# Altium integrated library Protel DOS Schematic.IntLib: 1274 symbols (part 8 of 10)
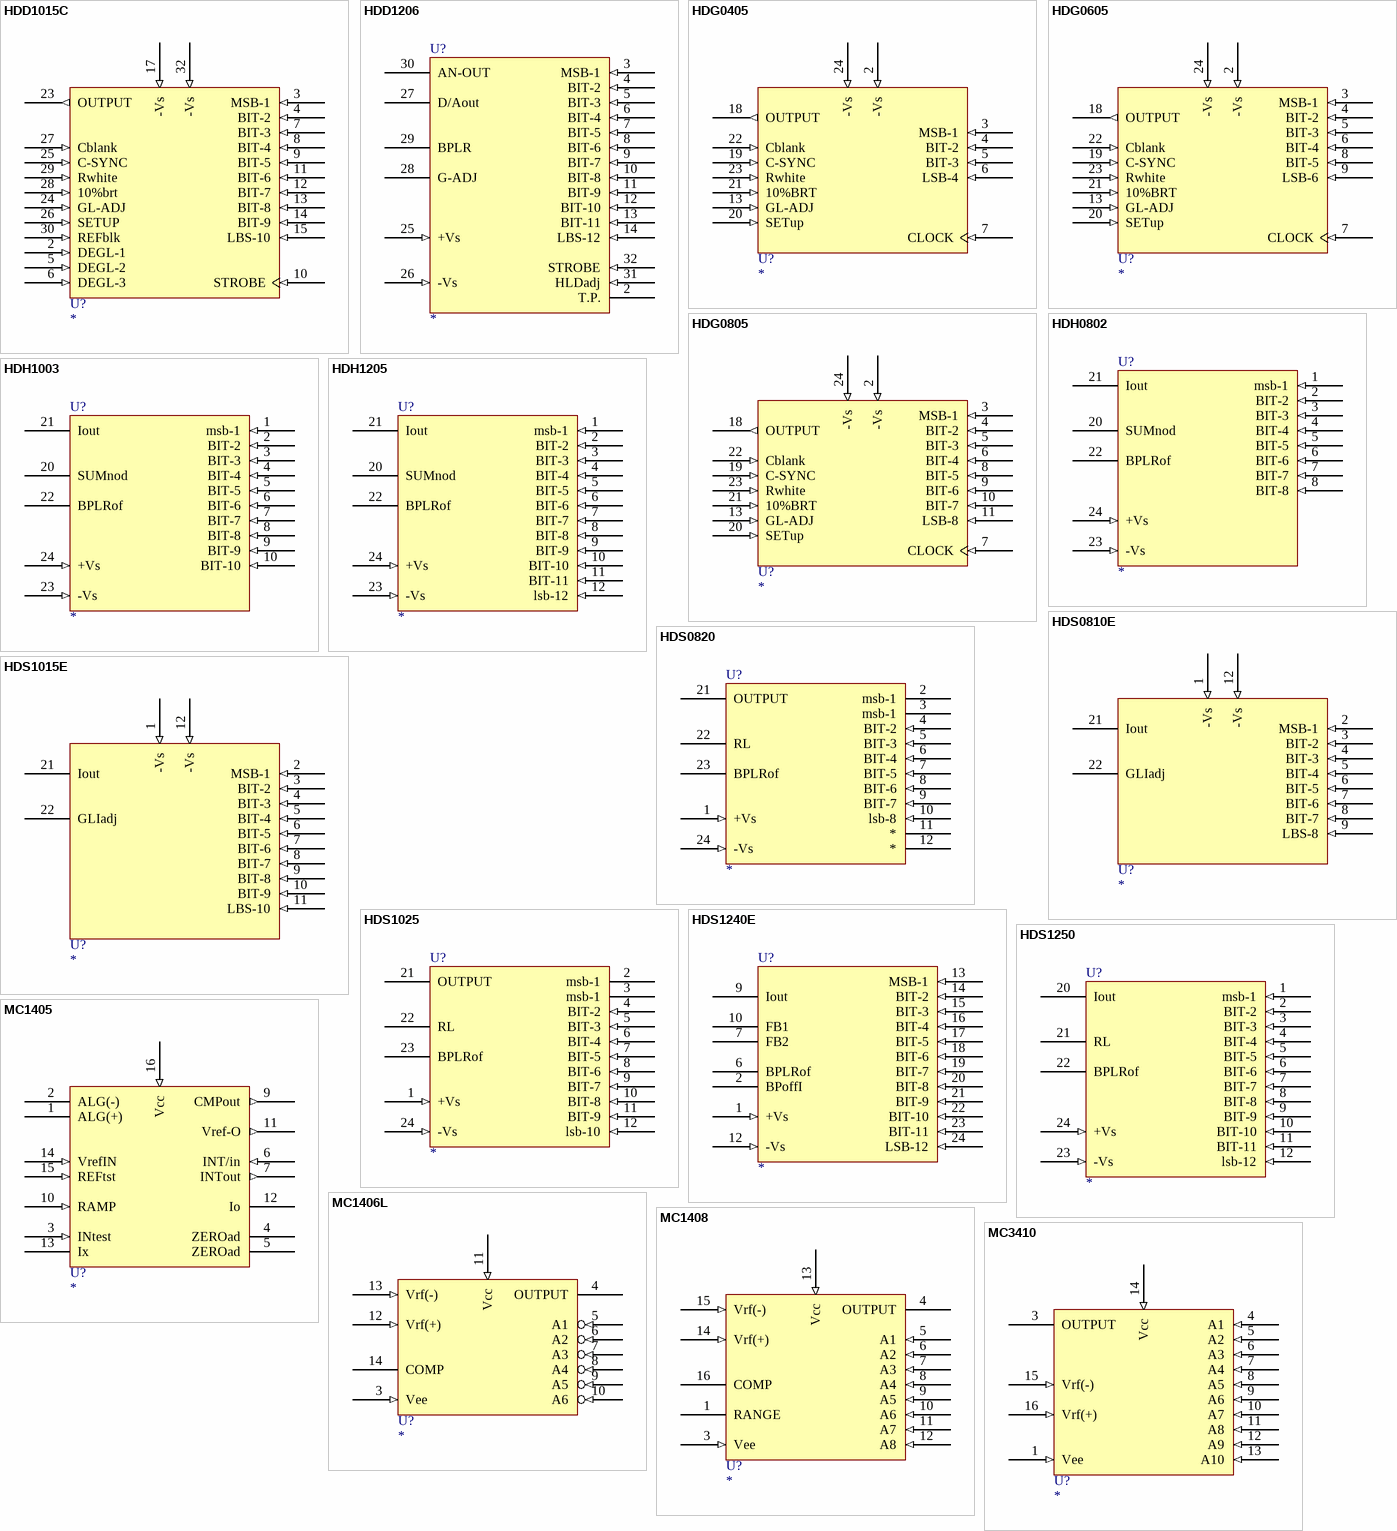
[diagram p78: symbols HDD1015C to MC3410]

## HDG0605
designator U?
footprint HY24
pins: 1 GND (power) hidden to GND, 2 -Vs (in), 3 MSB-1 (in), 4 BIT-2 (in), 5 BIT-3 (in), 6 BIT-4 (in), 7 CLOCK (in), 8 BIT-5 (in), 9 LSB-6 (in), 12 GND (power) hidden to GND, 13 GL-ADJ (in), 14 GND (power) hidden to GND, 15 GND (power) hidden to GND, 16 GND (power) hidden to GND, 17 GND (power) hidden to GND, 18 OUTPUT (out), 19 C-SYNC (in), 20 SETup (in), 21 10%BRT (in), 22 Cblank (in), 23 Rwhite (in), 24 -Vs (in)
2 alternate drawings of the same symbol

## HDG0805
designator U?
footprint HY24
pins: 1 GND (power) hidden to GND, 2 -Vs (in), 3 MSB-1 (in), 4 BIT-2 (in), 5 BIT-3 (in), 6 BIT-4 (in), 7 CLOCK (in), 8 BIT-5 (in), 9 BIT-6 (in), 10 BIT-7 (in), 11 LSB-8 (in), 12 GND (power) hidden to GND, 13 GL-ADJ (in), 14 GND (power) hidden to GND, 15 GND (power) hidden to GND, 16 GND (power) hidden to GND, 17 GND (power) hidden to GND, 18 OUTPUT (out), 19 C-SYNC (in), 20 SETup (in), 21 10%BRT (in), 22 Cblank (in), 23 Rwhite (in), 24 -Vs (in)
2 alternate drawings of the same symbol

## HDH0802
designator U?
footprint HY24
pins: 1 msb-1 (in), 2 BIT-2 (in), 3 BIT-3 (in), 4 BIT-4 (in), 5 BIT-5 (in), 6 BIT-6 (in), 7 BIT-7 (in), 8 BIT-8 (in), 9 GND (power) hidden to GND, 10 GND (power) hidden to GND, 11 GND (power) hidden to GND, 12 GND (power) hidden to GND, 13 GND (power) hidden to GND, 14 GND (power) hidden to GND, 15 GND (power) hidden to GND, 16 GND (power) hidden to GND, 17 GND (power) hidden to GND, 18 GND (power) hidden to GND, 19 GND (power) hidden to GND, 20 SUMnod, 21 Iout, 22 BPLRof, 23 -Vs (in), 24 +Vs (in)
2 alternate drawings of the same symbol

## HDH1003
designator U?
footprint HY24
pins: 1 msb-1 (in), 2 BIT-2 (in), 3 BIT-3 (in), 4 BIT-4 (in), 5 BIT-5 (in), 6 BIT-6 (in), 7 BIT-7 (in), 8 BIT-8 (in), 9 BIT-9 (in), 10 BIT-10 (in), 11 GND (power) hidden to GND, 12 GND (power) hidden to GND, 13 GND (power) hidden to GND, 14 GND (power) hidden to GND, 15 GND (power) hidden to GND, 16 GND (power) hidden to GND, 17 GND (power) hidden to GND, 18 GND (power) hidden to GND, 19 GND (power) hidden to GND, 20 SUMnod, 21 Iout, 22 BPLRof, 23 -Vs (in), 24 +Vs (in)
2 alternate drawings of the same symbol

## HDH1205
designator U?
footprint HY24
pins: 1 msb-1 (in), 2 BIT-2 (in), 3 BIT-3 (in), 4 BIT-4 (in), 5 BIT-5 (in), 6 BIT-6 (in), 7 BIT-7 (in), 8 BIT-8 (in), 9 BIT-9 (in), 10 BIT-10 (in), 11 BIT-11 (in), 12 lsb-12 (in), 13 GND (power) hidden to GND, 14 GND (power) hidden to GND, 15 GND (power) hidden to GND, 16 GND (power) hidden to GND, 17 GND (power) hidden to GND, 18 GND (power) hidden to GND, 19 GND (power) hidden to GND, 20 SUMnod, 21 Iout, 22 BPLRof, 23 -Vs (in), 24 +Vs (in)
2 alternate drawings of the same symbol

## HDS0810E
designator U?
footprint HY24
pins: 1 -Vs (in), 2 MSB-1 (in), 3 BIT-2 (in), 4 BIT-3 (in), 5 BIT-4 (in), 6 BIT-5 (in), 7 BIT-6 (in), 8 BIT-7 (in), 9 LBS-8 (in), 12 -Vs (in), 13 GND (power) hidden to GND, 14 GND (power) hidden to GND, 15 GND (power) hidden to GND, 16 GND (power) hidden to GND, 17 GND (power) hidden to GND, 18 GND (power) hidden to GND, 19 GND (power) hidden to GND, 20 GND (power) hidden to GND, 21 Iout, 22 GLIadj, 23 GND (power) hidden to GND, 24 GND (power) hidden to GND
2 alternate drawings of the same symbol

## HDS0820
designator U?
footprint HY24
pins: 1 +Vs (in), 2 msb-1, 3 msb-1, 4 BIT-2 (in), 5 BIT-3 (in), 6 BIT-4 (in), 7 BIT-5 (in), 8 BIT-6 (in), 9 BIT-7 (in), 10 lsb-8 (in), 11 *, 12 *, 13 GND (power) hidden to GND, 14 GND (power) hidden to GND, 15 GND (power) hidden to GND, 16 GND (power) hidden to GND, 17 GND (power) hidden to GND, 18 GND (power) hidden to GND, 19 GND (power) hidden to GND, 20 GND (power) hidden to GND, 21 OUTPUT, 22 RL, 23 BPLRof, 24 -Vs (in)
2 alternate drawings of the same symbol

## HDS1015E
designator U?
footprint HY24
pins: 1 -Vs (in), 2 MSB-1 (in), 3 BIT-2 (in), 4 BIT-3 (in), 5 BIT-4 (in), 6 BIT-5 (in), 7 BIT-6 (in), 8 BIT-7 (in), 9 BIT-8 (in), 10 BIT-9 (in), 11 LBS-10 (in), 12 -Vs (in), 13 GND (power) hidden to GND, 14 GND (power) hidden to GND, 15 GND (power) hidden to GND, 16 GND (power) hidden to GND, 17 GND (power) hidden to GND, 18 GND (power) hidden to GND, 19 GND (power) hidden to GND, 20 GND (power) hidden to GND, 21 Iout, 22 GLIadj, 23 GND (power) hidden to GND, 24 GND (power) hidden to GND
2 alternate drawings of the same symbol

## HDS1025
designator U?
footprint HY24
pins: 1 +Vs (in), 2 msb-1, 3 msb-1, 4 BIT-2 (in), 5 BIT-3 (in), 6 BIT-4 (in), 7 BIT-5 (in), 8 BIT-6 (in), 9 BIT-7 (in), 10 BIT-8 (in), 11 BIT-9 (in), 12 lsb-10 (in), 13 GND (power) hidden to GND, 14 GND (power) hidden to GND, 15 GND (power) hidden to GND, 16 GND (power) hidden to GND, 17 GND (power) hidden to GND, 18 GND (power) hidden to GND, 19 GND (power) hidden to GND, 20 GND (power) hidden to GND, 21 OUTPUT, 22 RL, 23 BPLRof, 24 -Vs (in)
2 alternate drawings of the same symbol

## HDS1240E
designator U?
footprint HY24
pins: 1 +Vs (in), 2 BPoffI, 3 GND (power) hidden to GND, 4 GND (power) hidden to GND, 5 GND (power) hidden to GND, 6 BPLRof, 7 FB2, 9 Iout, 10 FB1, 12 -Vs (in), 13 MSB-1 (in), 14 BIT-2 (in), 15 BIT-3 (in), 16 BIT-4 (in), 17 BIT-5 (in), 18 BIT-6 (in), 19 BIT-7 (in), 20 BIT-8 (in), 21 BIT-9 (in), 22 BIT-10 (in), 23 BIT-11 (in), 24 LSB-12 (in)
2 alternate drawings of the same symbol

## HDS1250
designator U?
footprint HY24
pins: 1 msb-1 (in), 2 BIT-2 (in), 3 BIT-3 (in), 4 BIT-4 (in), 5 BIT-5 (in), 6 BIT-6 (in), 7 BIT-7 (in), 8 BIT-8 (in), 9 BIT-9 (in), 10 BIT-10 (in), 11 BIT-11 (in), 12 lsb-12 (in), 13 GND (power) hidden to GND, 14 GND (power) hidden to GND, 15 GND (power) hidden to GND, 16 GND (power) hidden to GND, 17 GND (power) hidden to GND, 18 GND (power) hidden to GND, 19 GND (power) hidden to GND, 20 Iout, 21 RL, 22 BPLRof, 23 -Vs (in), 24 +Vs (in)
2 alternate drawings of the same symbol

## MC1405
designator U?
footprint DIP-16
pins: 1 ALG(+), 2 ALG(-), 3 INtest (in), 4 ZEROad, 5 ZEROad, 6 INT/in (in), 7 INTout (out), 8 GND (power) hidden to GND, 9 CMPout (out), 10 RAMP (in), 11 Vref-O (out), 12 Io, 13 Ix, 14 VrefIN (in), 15 REFtst (in), 16 Vcc (in)
2 alternate drawings of the same symbol

## MC1406L
designator U?
footprint DIP-14
pins: 2 GND (power) hidden to GND, 3 Vee (in), 4 OUTPUT, 5 A1 (in), 6 A2 (in), 7 A3 (in), 8 A4 (in), 9 A5 (in), 10 A6 (in), 11 Vcc (in), 12 Vrf(+) (in), 13 Vrf(-) (in), 14 COMP
2 alternate drawings of the same symbol

## MC1408
designator U?
footprint DIP-16
pins: 1 RANGE, 2 GND (power) hidden to GND, 3 Vee (in), 4 OUTPUT, 5 A1 (in), 6 A2 (in), 7 A3 (in), 8 A4 (in), 9 A5 (in), 10 A6 (in), 11 A7 (in), 12 A8 (in), 13 Vcc (in), 14 Vrf(+) (in), 15 Vrf(-) (in), 16 COMP
2 alternate drawings of the same symbol

## MC3410
designator U?
footprint DIP-16
pins: 1 Vee (in), 2 GND (power) hidden to GND, 3 OUTPUT, 4 A1 (in), 5 A2 (in), 6 A3 (in), 7 A4 (in), 8 A5 (in), 9 A6 (in), 10 A7 (in), 11 A8 (in), 12 A9 (in), 13 A10 (in), 14 Vcc (in), 15 Vrf(-) (in), 16 Vrf(+) (in)
2 alternate drawings of the same symbol

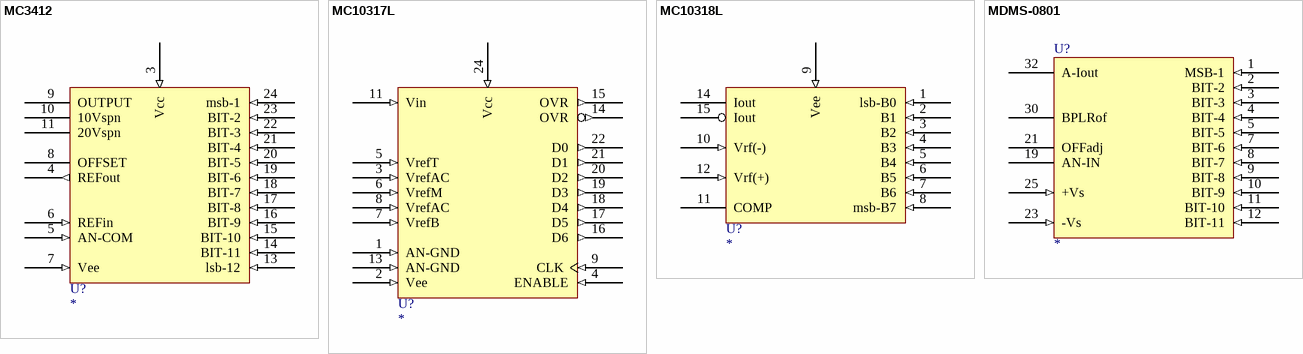
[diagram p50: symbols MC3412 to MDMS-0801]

## MC3412
designator U?
footprint DIP-24
pins: 3 Vcc (in), 4 REFout (out), 5 AN-COM (in), 6 REFin (in), 7 Vee (in), 8 OFFSET, 9 OUTPUT, 10 10Vspn, 11 20Vspn, 12 GND (power) hidden to GND, 13 lsb-12 (in), 14 BIT-11 (in), 15 BIT-10 (in), 16 BIT-9 (in), 17 BIT-8 (in), 18 BIT-7 (in), 19 BIT-6 (in), 20 BIT-5 (in), 21 BIT-4 (in), 22 BIT-3 (in), 23 BIT-2 (in), 24 msb-1 (in)
2 alternate drawings of the same symbol

## MC10317L
designator U?
footprint DIP-24
pins: 1 AN-GND (in), 2 Vee (in), 3 VrefAC (in), 4 ENABLE (in), 5 VrefT (in), 6 VrefM (in), 7 VrefB (in), 8 VrefAC (in), 9 CLK (in), 11 Vin (in), 13 AN-GND (in), 14 OVR (out), 15 OVR (out), 16 D6 (out), 17 D5 (out), 18 D4 (out), 19 D3 (out), 20 D2 (out), 21 D1 (out), 22 D0 (out), 23 GND (power) hidden to GND, 24 Vcc (in)
2 alternate drawings of the same symbol

## MC10318L
designator U?
footprint DIP-16
pins: 1 lsb-B0 (in), 2 B1 (in), 3 B2 (in), 4 B3 (in), 5 B4 (in), 6 B5 (in), 7 B6 (in), 8 msb-B7 (in), 9 Vee (in), 10 Vrf(-) (in), 11 COMP, 12 Vrf(+) (in), 14 Iout, 15 Iout, 16 GND (power) hidden to GND
2 alternate drawings of the same symbol

## MDMS-0801
designator U?
footprint HYB32
pins: 1 MSB-1 (in), 2 BIT-2 (in), 3 BIT-3 (in), 4 BIT-4 (in), 5 BIT-5 (in), 7 BIT-6 (in), 8 BIT-7 (in), 9 BIT-8 (in), 10 BIT-9 (in), 11 BIT-10 (in), 12 BIT-11 (in), 19 AN-IN, 21 OFFadj, 23 -Vs (in), 25 +Vs (in), 28 GND (power) hidden to GND, 30 BPLRof, 32 A-Iout
2 alternate drawings of the same symbol


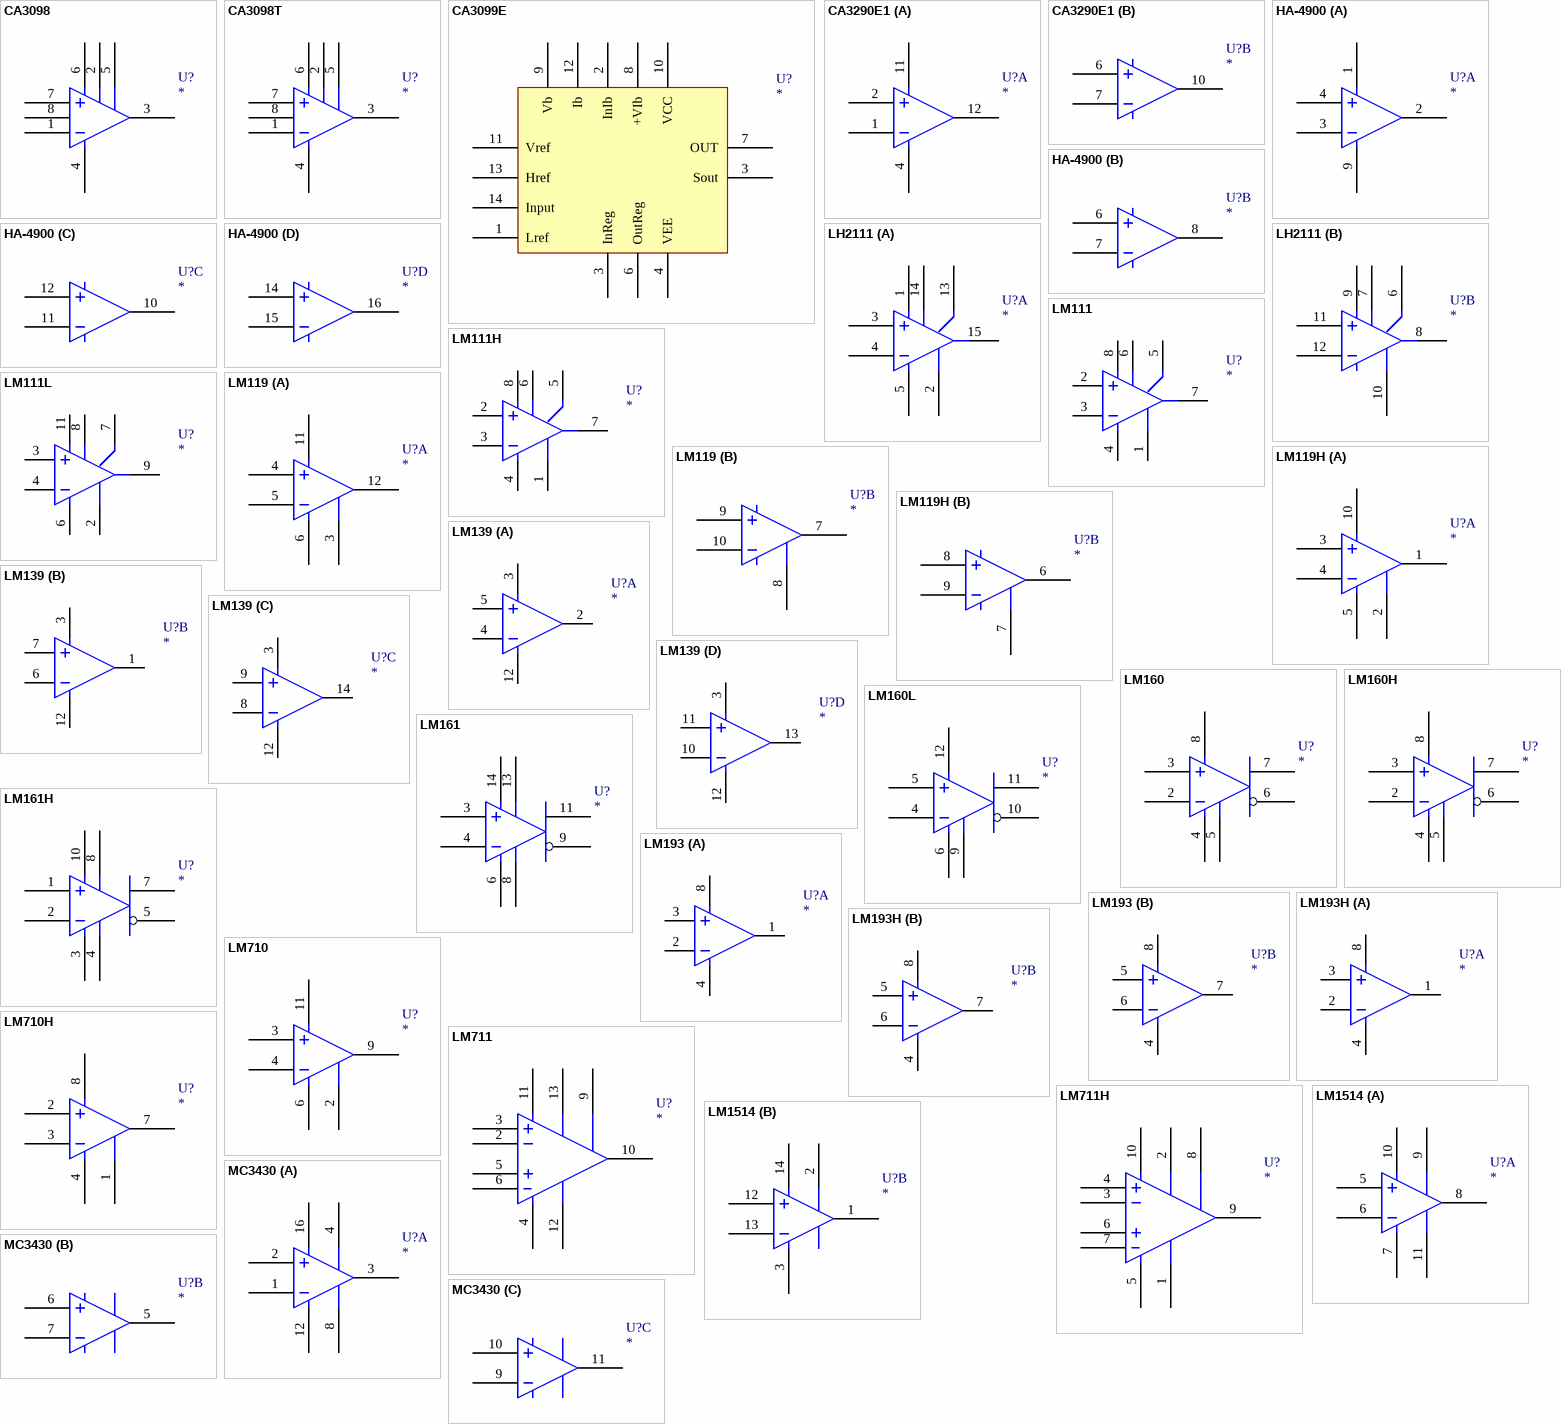
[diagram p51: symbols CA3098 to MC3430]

## CA3098
designator U?
footprint DIP-8
pins: 1, 2, 3, 4, 5, 6, 7, 8
2 alternate drawings of the same symbol

## CA3098T
designator U?
footprint METAL8
pins: 1, 2, 3, 4, 5, 6, 7, 8
2 alternate drawings of the same symbol

## CA3099E
designator U?
footprint DIP-14
pins: 1 Lref, 2 InIb, 3 Sout, 3 InReg, 4 VEE, 6 OutReg, 7 OUT, 8 +VIb, 9 Vb, 10 VCC, 11 Vref, 12 Ib, 13 Href, 14 Input
2 alternate drawings of the same symbol

## CA3290E1
designator U?
footprint DIP-14
part A pins: 1, 2, 4, 11, 12
part B pins: 6, 7, 10
2 alternate drawings of the same symbol

## HA-4900
designator U?
footprint DIP-16
part A pins: 1, 2, 3, 4, 9
part B pins: 6, 7, 8
part C pins: 10, 11, 12
part D pins: 14, 15, 16
2 alternate drawings of the same symbol

## LH2111
designator U?
footprint DIP-16
part A pins: 1, 2, 3, 4, 5, 13, 14, 15
part B pins: 6, 7, 8, 9, 10, 11, 12
2 alternate drawings of the same symbol

## LM111
designator U?
footprint DIP-8
pins: 1, 2, 3, 4, 5, 6, 7, 8
2 alternate drawings of the same symbol

## LM111H
designator U?
footprint METAL8
pins: 1, 2, 3, 4, 5, 6, 7, 8
2 alternate drawings of the same symbol

## LM111L
designator U?
footprint DIP-14
pins: 2, 3, 4, 6, 7, 8, 9, 11
2 alternate drawings of the same symbol

## LM119
designator U?
footprint DIP-14
part A pins: 3, 4, 5, 6, 11, 12
part B pins: 7, 8, 9, 10
2 alternate drawings of the same symbol

## LM119H
designator U?
footprint METAL10
part A pins: 1, 2, 3, 4, 5, 10
part B pins: 6, 7, 8, 9
2 alternate drawings of the same symbol

## LM139
designator U?
footprint DIP-14
part A pins: 2, 3, 4, 5, 12
part B pins: 1, 3, 6, 7, 12
part C pins: 3, 8, 9, 12, 14
part D pins: 3, 10, 11, 12, 13
2 alternate drawings of the same symbol

## LM160
designator U?
footprint DIP-8
pins: 2, 3, 4, 5, 6, 7, 8
2 alternate drawings of the same symbol

## LM160H
designator U?
footprint METAL8
pins: 2, 3, 4, 5, 6, 7, 8
2 alternate drawings of the same symbol

## LM160L
designator U?
footprint DIP-14
pins: 4, 5, 6, 9, 10, 11, 12
2 alternate drawings of the same symbol

## LM161
designator U?
footprint DIP-14
pins: 3, 4, 6, 8, 9, 11, 13, 14
2 alternate drawings of the same symbol

## LM161H
designator U?
footprint METAL10
pins: 1, 2, 3, 4, 5, 7, 8, 10
2 alternate drawings of the same symbol

## LM193
designator U?
footprint DIP-8
part A pins: 1, 2, 3, 4, 8
part B pins: 4, 5, 6, 7, 8
2 alternate drawings of the same symbol

## LM193H
designator U?
footprint METAL10
part A pins: 1, 2, 3, 4, 8
part B pins: 4, 5, 6, 7, 8
2 alternate drawings of the same symbol

## LM710
designator U?
footprint DIP-14
pins: 2, 3, 4, 6, 9, 11
2 alternate drawings of the same symbol

## LM710H
designator U?
footprint METAL8
pins: 1, 2, 3, 4, 7, 8
2 alternate drawings of the same symbol

## LM711
designator U?
footprint DIP-14
pins: 2, 3, 4, 5, 6, 9, 10, 11, 12, 13
2 alternate drawings of the same symbol

## LM711H
designator U?
footprint METAL10
pins: 1, 2, 3, 4, 5, 6, 7, 8, 9, 10
2 alternate drawings of the same symbol

## LM1514
designator U?
footprint DIP-14
part A pins: 5, 6, 7, 8, 9, 10, 11
part B pins: 1, 2, 3, 12, 13, 14
2 alternate drawings of the same symbol

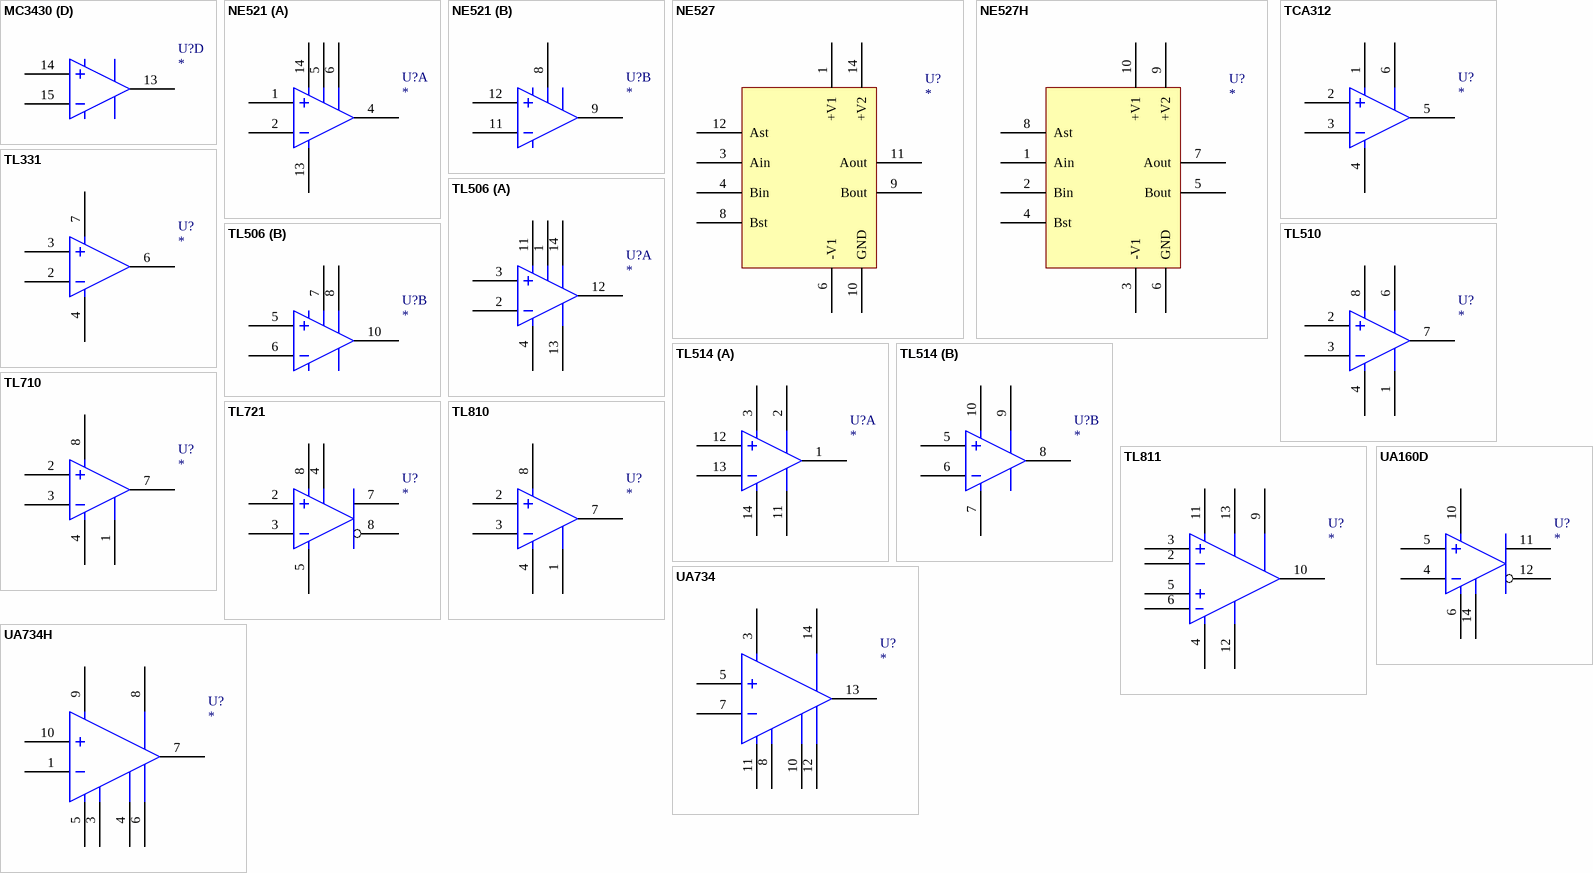
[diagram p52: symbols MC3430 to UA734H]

## MC3430
designator U?
footprint DIP-16
part A pins: 1, 2, 3, 4, 8, 12, 16
part B pins: 5, 6, 7
part C pins: 9, 10, 11
part D pins: 13, 14, 15
2 alternate drawings of the same symbol

## NE521
designator U?
footprint DIP-14
part A pins: 1, 2, 4, 5, 6, 13, 14
part B pins: 8, 9, 11, 12
2 alternate drawings of the same symbol

## NE527
designator U?
footprint DIP-14
pins: 1 +V1, 3 Ain, 4 Bin, 6 -V1, 8 Bst, 9 Bout, 10 GND, 11 Aout, 12 Ast, 14 +V2
2 alternate drawings of the same symbol

## NE527H
designator U?
footprint METAL10
pins: 1 Ain, 2 Bin, 3 -V1, 4 Bst, 5 Bout, 6 GND, 7 Aout, 8 Ast, 9 +V2, 10 +V1
2 alternate drawings of the same symbol

## TCA312
designator U?
footprint DIP-6
pins: 1, 2, 3, 4, 5, 6
2 alternate drawings of the same symbol

## TL331
designator U?
footprint DIP-8
pins: 2, 3, 4, 6, 7
2 alternate drawings of the same symbol

## TL506
designator U?
footprint DIP-14
part A pins: 1, 2, 3, 4, 11, 12, 13, 14
part B pins: 5, 6, 7, 8, 10
2 alternate drawings of the same symbol

## TL510
designator U?
footprint DIP-8
pins: 1, 2, 3, 4, 6, 7, 8
2 alternate drawings of the same symbol

## TL514
designator U?
footprint DIP-14
part A pins: 1, 2, 3, 11, 12, 13, 14
part B pins: 5, 6, 7, 8, 9, 10
2 alternate drawings of the same symbol

## TL710
designator U?
footprint DIP-8
pins: 1, 2, 3, 4, 7, 8
2 alternate drawings of the same symbol

## TL721
designator U?
footprint DIP-8
pins: 2, 3, 4, 5, 7, 8, 8
2 alternate drawings of the same symbol

## TL810
designator U?
footprint DIP-8
pins: 1, 2, 3, 4, 7, 8
2 alternate drawings of the same symbol

## TL811
designator U?
footprint DIP-14
pins: 2, 3, 4, 5, 6, 9, 10, 11, 12, 13
2 alternate drawings of the same symbol

## UA160D
designator U?
footprint DIP-14
pins: 4, 5, 6, 10, 11, 12, 14
2 alternate drawings of the same symbol

## UA734
designator U?
footprint DIP-14
pins: 3, 5, 7, 8, 10, 11, 12, 13, 14
2 alternate drawings of the same symbol

## UA734H
designator U?
footprint METAL10
pins: 1, 3, 4, 5, 6, 7, 8, 9, 10
2 alternate drawings of the same symbol


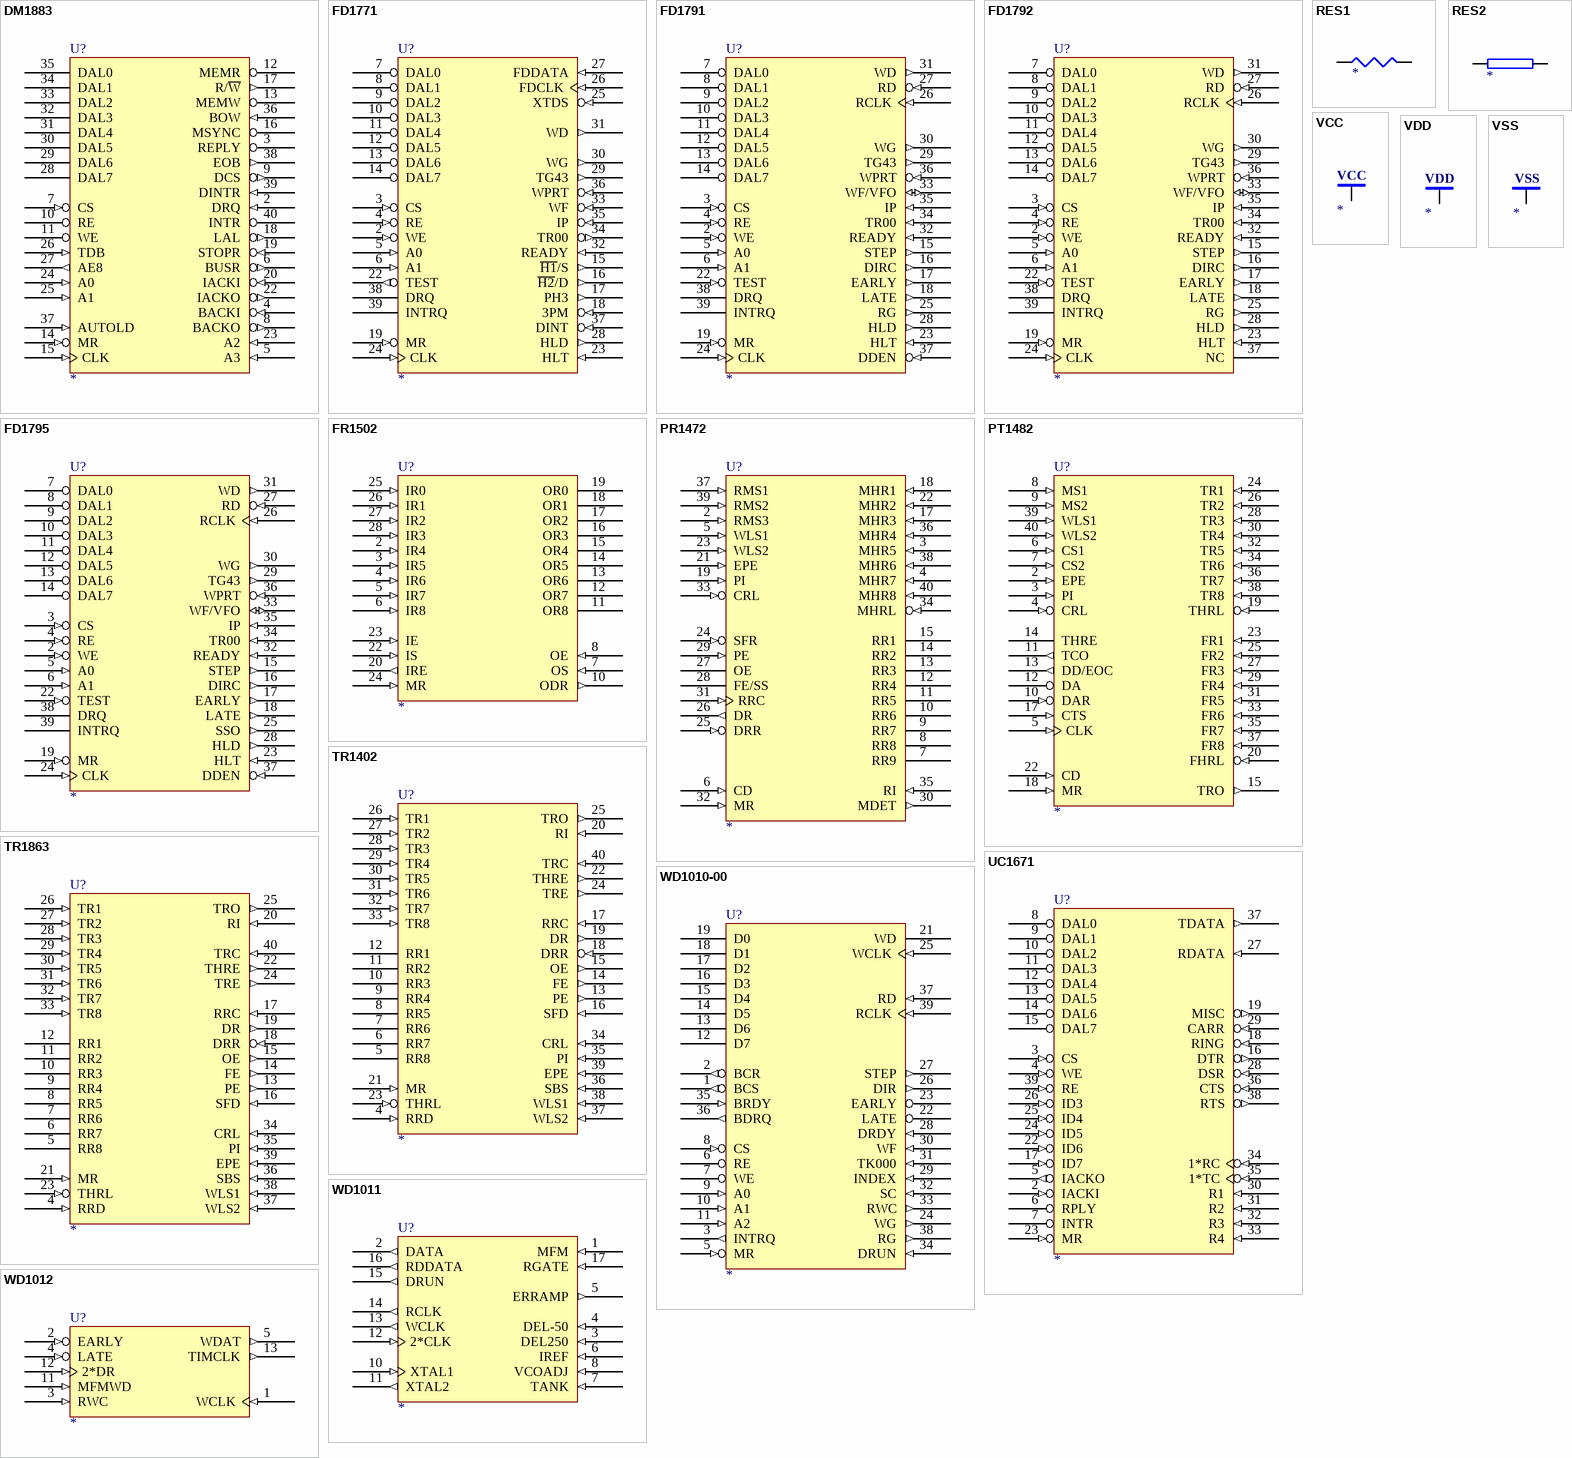
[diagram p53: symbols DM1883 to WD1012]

## DM1883
designator U?
footprint DIP-40
pins: 1 GND (power) hidden to GND, 2 DRQ (in), 3 REPLY (oc), 4 BACKI (in), 5 A3 (in), 6 BUSR (out), 7 CS (in), 8 BACKO (out), 9 DCS (out), 10 RE (oc), 11 WE (oc), 12 MEMR (oc), 13 MEMW (oc), 14 MR (in), 15 CLK (in), 16 MSYNC (oc), 17 R/~{W} (out), 18 LAL (out), 19 STOPR (in), 20 IACKI (in), 21 VCC (power) hidden to VCC, 22 IACKO (out), 23 A2 (in), 24 A0 (in), 25 A1 (in), 26 TDB (in), 27 AE8 (out), 28 DAL7 (hiz), 29 DAL6 (hiz), 30 DAL5 (hiz), 31 DAL4 (hiz), 32 DAL3 (hiz), 33 DAL2 (hiz), 34 DAL1 (hiz), 35 DAL0 (hiz), 36 BOW (in), 37 AUTOLD (in), 38 EOB (out), 39 DINTR (in), 40 INTR (oc)
2 alternate drawings of the same symbol

## FD1771
designator U?
footprint DIP-40
pins: 1 -5 (power) hidden to -5, 2 WE (in), 3 CS (in), 4 RE (in), 5 A0 (in), 6 A1 (in), 7 DAL0 (hiz), 8 DAL1 (hiz), 9 DAL2 (hiz), 10 DAL3 (hiz), 11 DAL4 (hiz), 12 DAL5 (hiz), 13 DAL6 (hiz), 14 DAL7 (hiz), 15 ~{H1}/S (out), 16 ~{H2}/D (out), 17 PH3 (out), 18 3PM (in), 19 MR (in), 20 GND (power) hidden to GND, 21 VCC (power) hidden to VCC, 22 TEST (out), 23 HLT (in), 24 CLK (in), 25 XTDS (in), 26 FDCLK (in), 27 FDDATA (in), 28 HLD (out), 29 TG43 (out), 30 WG (out), 31 WD (out), 32 READY (in), 33 WF (in), 34 TR00 (out), 35 IP (in), 36 WPRT (in), 37 DINT (in), 38 DRQ (oc), 39 INTRQ (oc), 40 +12 (power) hidden to +12
2 alternate drawings of the same symbol

## FD1791
designator U?
footprint DIP-40
pins: 2 WE (in), 3 CS (in), 4 RE (in), 5 A0 (in), 6 A1 (in), 7 DAL0 (hiz), 8 DAL1 (hiz), 9 DAL2 (hiz), 10 DAL3 (hiz), 11 DAL4 (hiz), 12 DAL5 (hiz), 13 DAL6 (hiz), 14 DAL7 (hiz), 15 STEP (out), 16 DIRC (out), 17 EARLY (out), 18 LATE (out), 19 MR (in), 20 GND (power) hidden to GND, 21 VCC (power) hidden to VCC, 22 TEST (in), 23 HLT (in), 24 CLK (in), 25 RG (out), 26 RCLK (in), 27 RD (in), 28 HLD (out), 29 TG43 (out), 30 WG (out), 31 WD (out), 32 READY (in), 33 WF/VFO (io), 34 TR00 (in), 35 IP (in), 36 WPRT (in), 37 DDEN (in), 38 DRQ (oc), 39 INTRQ (oc), 40 +12 (power) hidden to +12
2 alternate drawings of the same symbol

## FD1792
designator U?
footprint DIP-40
pins: 2 WE (in), 3 CS (in), 4 RE (in), 5 A0 (in), 6 A1 (in), 7 DAL0 (hiz), 8 DAL1 (hiz), 9 DAL2 (hiz), 10 DAL3 (hiz), 11 DAL4 (hiz), 12 DAL5 (hiz), 13 DAL6 (hiz), 14 DAL7 (hiz), 15 STEP (out), 16 DIRC (out), 17 EARLY (out), 18 LATE (out), 19 MR (in), 20 GND (power) hidden to GND, 21 VCC (power) hidden to VCC, 22 TEST (in), 23 HLT (in), 24 CLK (in), 25 RG (out), 26 RCLK (in), 27 RD (in), 28 HLD (out), 29 TG43 (out), 30 WG (out), 31 WD (out), 32 READY (in), 33 WF/VFO (io), 34 TR00 (in), 35 IP (in), 36 WPRT (in), 37 NC, 38 DRQ (oc), 39 INTRQ (oc), 40 +12 (power) hidden to +12
2 alternate drawings of the same symbol

## FD1795
designator U?
footprint DIP-40
pins: 2 WE (in), 3 CS (in), 4 RE (in), 5 A0 (in), 6 A1 (in), 7 DAL0 (hiz), 8 DAL1 (hiz), 9 DAL2 (hiz), 10 DAL3 (hiz), 11 DAL4 (hiz), 12 DAL5 (hiz), 13 DAL6 (hiz), 14 DAL7 (hiz), 15 STEP (out), 16 DIRC (out), 17 EARLY (out), 18 LATE (out), 19 MR (in), 20 GND (power) hidden to GND, 21 VCC (power) hidden to VCC, 22 TEST (in), 23 HLT (in), 24 CLK (in), 25 SSO (out), 26 RCLK (in), 27 RD (in), 28 HLD (out), 29 TG43 (out), 30 WG (out), 31 WD (out), 32 READY (in), 33 WF/VFO (io), 34 TR00 (in), 35 IP (in), 36 WPRT (in), 37 DDEN (in), 38 DRQ (oc), 39 INTRQ (oc), 40 +12 (power) hidden to +12
2 alternate drawings of the same symbol

## FR1502
designator U?
footprint DIP-28
pins: 1 VCC (power) hidden to VCC, 2 IR4 (in), 3 IR5 (in), 4 IR6 (in), 5 IR7 (in), 6 IR8 (in), 7 OS (in), 8 OE (in), 9 +12 (power) hidden to +12, 10 ODR (out), 11 OR8 (hiz), 12 OR7 (hiz), 13 OR6 (hiz), 14 OR5 (hiz), 15 OR4 (hiz), 16 OR3 (hiz), 17 OR2 (hiz), 18 OR1 (hiz), 19 OR0 (hiz), 20 IRE (out), 21 GND (power) hidden to GND, 22 IS (in), 23 IE (in), 24 MR (in), 25 IR0 (in), 26 IR1 (in), 27 IR2 (in), 28 IR3 (in)
2 alternate drawings of the same symbol

## PR1472
designator U?
footprint DIP-40
pins: 1 VCC (power) hidden to VCC, 2 RMS3 (in), 3 MHR5 (in), 4 MHR7 (in), 5 WLS1 (in), 6 CD (in), 7 RR9 (hiz), 8 RR8 (hiz), 9 RR7 (hiz), 10 RR6 (hiz), 11 RR5 (hiz), 12 RR4 (hiz), 13 RR3 (hiz), 14 RR2 (hiz), 15 RR1 (hiz), 16 +12 (power) hidden to +12, 17 MHR3 (in), 18 MHR1 (in), 19 PI (in), 20 GND (power) hidden to GND, 21 EPE (in), 22 MHR2 (in), 23 WLS2 (in), 24 SFR (in), 25 DRR (in), 26 DR (out), 27 OE (hiz), 28 FE/SS (hiz), 29 PE (in), 30 MDET (out), 31 RRC (in), 32 MR (in), 33 CRL (in), 34 MHRL (in), 35 RI (in), 36 MHR4 (in), 37 RMS1 (in), 38 MHR6 (in), 39 RMS2 (in), 40 MHR8 (in)
2 alternate drawings of the same symbol

## PT1482
designator U?
footprint DIP-40
pins: 1 VCC (power) hidden to VCC, 2 EPE (in), 3 PI (in), 4 CRL (in), 5 CLK (in), 6 CS1 (in), 7 CS2 (in), 8 MS1 (in), 9 MS2 (in), 10 DAR (in), 11 TCO (out), 12 DA (hiz), 13 DD/EOC (out), 14 THRE (hiz), 15 TRO (out), 16 +12 (power) hidden to +12, 17 CTS (in), 18 MR (in), 19 THRL (in), 20 FHRL (in), 21 GND (power) hidden to GND, 22 CD (in), 23 FR1 (in), 24 TR1 (in), 25 FR2 (in), 26 TR2 (in), 27 FR3 (in), 28 TR3 (in), 29 FR4 (in), 30 TR4 (in), 31 FR5 (in), 32 TR5 (in), 33 FR6 (in), 34 TR6 (in), 35 FR7 (in), 36 TR7 (in), 37 FR8 (in), 38 TR8 (in), 39 WLS1 (in), 40 WLS2 (in)
2 alternate drawings of the same symbol

## RES1
designator ?
pins: 1, 2
2 alternate drawings of the same symbol

## RES2
designator ?
pins: 1, 2
2 alternate drawings of the same symbol

## TR1402
designator U?
footprint DIP-40
pins: 1 VCC (power) hidden to VCC, 2 +12 (power) hidden to +12, 3 GND (power) hidden to GND, 4 RRD (in), 5 RR8 (hiz), 6 RR7 (hiz), 7 RR6 (hiz), 8 RR5 (hiz), 9 RR4 (hiz), 10 RR3 (hiz), 11 RR2 (hiz), 12 RR1 (hiz), 13 PE (out), 14 FE (out), 15 OE (out), 16 SFD (in), 17 RRC (in), 18 DRR (in), 19 DR (out), 20 RI (in), 21 MR (in), 22 THRE (out), 23 THRL (in), 24 TRE (out), 25 TRO (out), 26 TR1 (in), 27 TR2 (in), 28 TR3 (in), 29 TR4 (in), 30 TR5 (in), 31 TR6 (in), 32 TR7 (in), 33 TR8 (in), 34 CRL (in), 35 PI (in), 36 SBS (in), 37 WLS2 (in), 38 WLS1 (in), 39 EPE (in), 40 TRC (in)
2 alternate drawings of the same symbol

## TR1863
designator U?
footprint DIP-40
pins: 1 VCC (power) hidden to VCC, 3 GND (power) hidden to GND, 4 RRD (in), 5 RR8 (hiz), 6 RR7 (hiz), 7 RR6 (hiz), 8 RR5 (hiz), 9 RR4 (hiz), 10 RR3 (hiz), 11 RR2 (hiz), 12 RR1 (hiz), 13 PE (out), 14 FE (out), 15 OE (out), 16 SFD (in), 17 RRC (in), 18 DRR (in), 19 DR (out), 20 RI (in), 21 MR (in), 22 THRE (out), 23 THRL (in), 24 TRE (out), 25 TRO (out), 26 TR1 (in), 27 TR2 (in), 28 TR3 (in), 29 TR4 (in), 30 TR5 (in), 31 TR6 (in), 32 TR7 (in), 33 TR8 (in), 34 CRL (in), 35 PI (in), 36 SBS (in), 37 WLS2 (in), 38 WLS1 (in), 39 EPE (in), 40 TRC (in)
2 alternate drawings of the same symbol

## UC1671
designator U?
footprint DIP-40
pins: 1 -5 (power) hidden to -5, 2 IACKI (in), 3 CS (in), 4 WE (in), 5 IACKO (out), 6 RPLY (oc), 7 INTR (oc), 8 DAL0 (hiz), 9 DAL1 (hiz), 10 DAL2 (hiz), 11 DAL3 (hiz), 12 DAL4 (hiz), 13 DAL5 (hiz), 14 DAL6 (hiz), 15 DAL7 (hiz), 16 DTR (out), 17 ID7 (in), 18 RING (in), 19 MISC (out), 20 GND (power) hidden to GND, 21 VCC (power) hidden to VCC, 22 ID6 (in), 23 MR (in), 24 ID5 (in), 25 ID4 (in), 26 ID3 (in), 27 RDATA (in), 28 DSR (in), 29 CARR (in), 30 R1 (in), 31 R2 (in), 32 R3 (in), 33 R4 (in), 34 1*RC (in), 35 1*TC (in), 36 CTS (in), 37 TDATA (out), 38 RTS (out), 39 RE (in), 40 +12 (power) hidden to +12
2 alternate drawings of the same symbol

## VCC
designator ?
pins: 1 (power)
2 alternate drawings of the same symbol

## VDD
designator ?
pins: 1 (power)
2 alternate drawings of the same symbol

## VSS
designator ?
pins: 1 (power)
2 alternate drawings of the same symbol

## WD1010-00
designator U?
footprint DIP-40
pins: 1 BCS (out), 2 BCR (out), 3 INTRQ (out), 5 MR (in), 6 RE (hiz), 7 WE (hiz), 8 CS (in), 9 A0 (in), 10 A1 (in), 11 A2 (in), 12 D7 (hiz), 13 D6 (hiz), 14 D5 (hiz), 15 D4 (hiz), 16 D3 (hiz), 17 D2 (hiz), 18 D1 (hiz), 19 D0 (hiz), 20 GND (power) hidden to GND, 21 WD (oc), 22 LATE (oc), 23 EARLY (oc), 24 WG (out), 25 WCLK (in), 26 DIR (out), 27 STEP (out), 28 DRDY (in), 29 INDEX (in), 30 WF (in), 31 TK000 (in), 32 SC (in), 33 RWC (out), 34 DRUN (in), 35 BRDY (in), 36 BDRQ (out), 37 RD (in), 38 RG (out), 39 RCLK (in), 40 VCC (power) hidden to VCC
2 alternate drawings of the same symbol

## WD1011
designator U?
footprint DIP-18
pins: 1 MFM (in), 2 DATA (out), 3 DEL250 (in), 4 DEL-50 (in), 5 ERRAMP (out), 6 IREF (in), 7 TANK (in), 8 VCOADJ (in), 9 GND (power) hidden to GND, 10 XTAL1 (in), 11 XTAL2 (out), 12 2*CLK (in), 13 WCLK (out), 14 RCLK (out), 15 DRUN (out), 16 RDDATA (out), 17 RGATE (in), 18 VCC (power) hidden to VCC
2 alternate drawings of the same symbol

## WD1012
designator U?
footprint DIP-14
pins: 1 WCLK (in), 2 EARLY (in), 3 RWC (in), 4 LATE (in), 5 WDAT (out), 7 GND (power) hidden to GND, 11 MFMWD (in), 12 2*DR (in), 13 TIMCLK (out), 14 VCC (power) hidden to VCC
2 alternate drawings of the same symbol

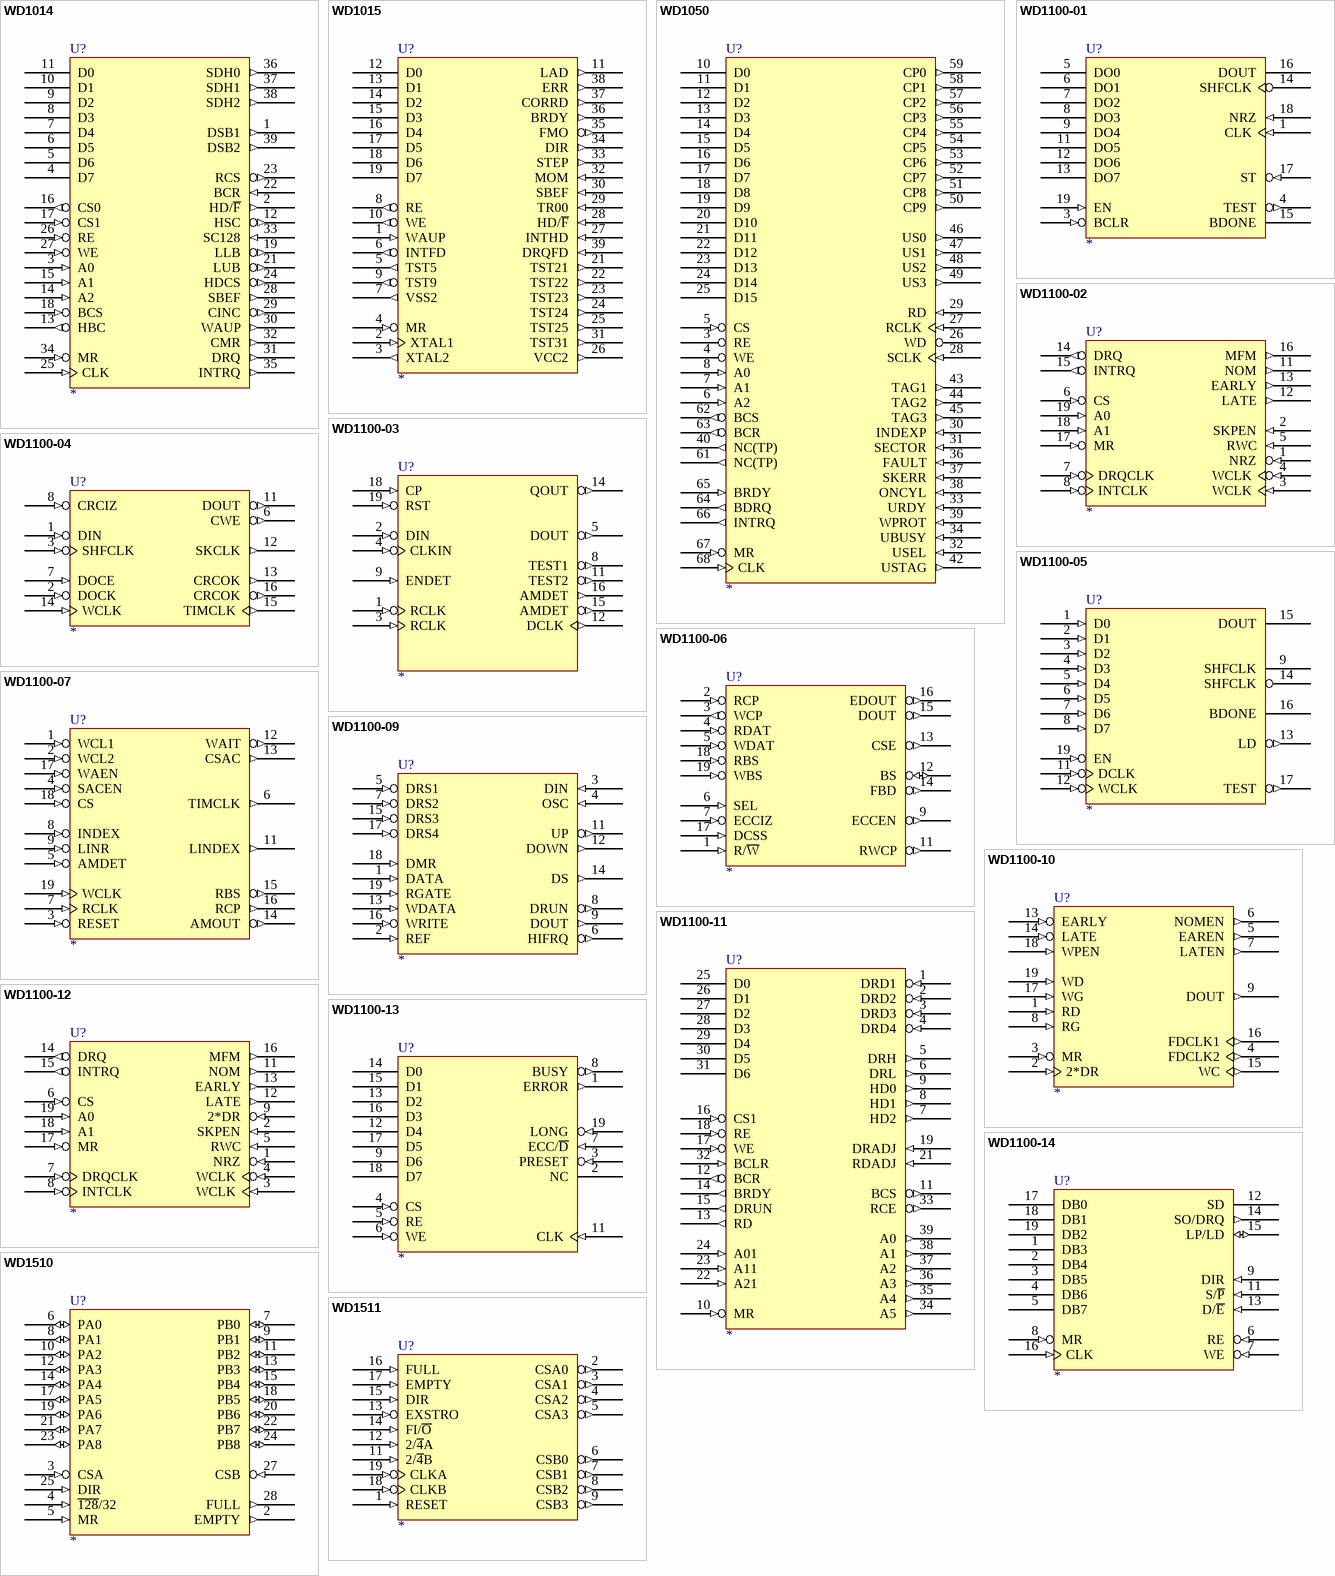
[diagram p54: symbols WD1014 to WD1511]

## WD1014
designator U?
footprint DIP-40
pins: 1 DSB1 (out), 2 HD/~{F} (out), 3 A0 (in), 4 D7 (hiz), 5 D6 (hiz), 6 D5 (hiz), 7 D4 (hiz), 8 D3 (hiz), 9 D2 (hiz), 10 D1 (hiz), 11 D0 (hiz), 12 HSC (out), 13 HBC (out), 14 A2 (in), 15 A1 (in), 16 CS0 (out), 17 CS1 (in), 18 BCS (in), 19 LLB (out), 20 GND (power) hidden to GND, 21 LUB (out), 22 BCR (in), 23 RCS (out), 24 HDCS (out), 25 CLK (in), 26 RE (in), 27 WE (in), 28 SBEF (out), 29 CINC (out), 30 WAUP (out), 31 DRQ (out), 32 CMR (out), 33 SC128 (in), 34 MR (in), 35 INTRQ (out), 36 SDH0 (out), 37 SDH1 (out), 38 SDH2 (out), 39 DSB2 (out), 40 VCC (power) hidden to VCC
2 alternate drawings of the same symbol

## WD1015
designator U?
footprint DIP-40
pins: 1 WAUP (in), 2 XTAL1 (in), 3 XTAL2 (out), 4 MR (in), 5 TST5 (out), 6 INTFD (out), 7 VSS2 (out), 8 RE (out), 9 TST9 (out), 10 WE (out), 11 LAD (out), 12 D0 (hiz), 13 D1 (hiz), 14 D2 (hiz), 15 D3 (hiz), 16 D4 (hiz), 17 D5 (hiz), 18 D6 (hiz), 19 D7 (hiz), 20 GND (power) hidden to GND, 21 TST21 (out), 22 TST22 (out), 23 TST23 (out), 24 TST24 (out), 25 TST25 (out), 26 VCC2 (out), 27 INTHD (in), 28 HD/~{F} (in), 29 TR00 (in), 30 SBEF (in), 31 TST31 (out), 32 MOM (in), 33 STEP (out), 34 DIR (out), 35 FMO (out), 36 BRDY (out), 37 CORRD (out), 38 ERR (out), 39 DRQFD (in), 40 VCC (power) hidden to VCC
2 alternate drawings of the same symbol

## WD1050
designator U?
footprint JEDECA-68
pins: 1 VCC (power) hidden to VCC, 3 RE (hiz), 4 WE (hiz), 5 CS (in), 6 A2 (in), 7 A1 (in), 8 A0 (in), 10 D0 (hiz), 11 D1 (hiz), 12 D2 (hiz), 13 D3 (hiz), 14 D4 (hiz), 15 D5 (hiz), 16 D6 (hiz), 17 D7 (hiz), 18 D8 (hiz), 19 D9 (hiz), 20 D10 (hiz), 21 D11 (hiz), 22 D12 (hiz), 23 D13 (hiz), 24 D14 (hiz), 25 D15 (hiz), 26 WD (oc), 27 RCLK (in), 28 SCLK (in), 29 RD (in), 30 INDEXP (in), 31 SECTOR (in), 32 USEL (in), 33 URDY (in), 34 UBUSY (in), 35 GND (power) hidden to GND, 36 FAULT (in), 37 SKERR (in), 38 ONCYL (in), 39 WPROT (in), 40 NC(TP) (out), 42 USTAG (out), 43 TAG1 (out), 44 TAG2 (out), 45 TAG3 (out), 46 US0 (out), 47 US1 (out), 48 US2 (out), 49 US3 (out), 50 CP9 (out), 51 CP8 (out), 52 CP7 (out), 53 CP6 (out), 54 CP5 (out), 55 CP4 (out), 56 CP3 (out), 57 CP2 (out), 58 CP1 (out), 59 CP0 (out), 61 NC(TP) (out), 62 BCS (out), 63 BCR (out), 64 BDRQ (out), 65 BRDY (in), 66 INTRQ (out), 67 MR (in), 68 CLK (in)
2 alternate drawings of the same symbol

## WD1100-01
designator U?
footprint DIP-20
pins: 1 CLK (in), 3 BCLR (in), 4 TEST (out), 5 DO0 (hiz), 6 DO1 (hiz), 7 DO2 (hiz), 8 DO3 (hiz), 9 DO4 (hiz), 10 GND (power) hidden to GND, 11 DO5 (hiz), 12 DO6 (hiz), 13 DO7 (hiz), 14 SHFCLK (hiz), 15 BDONE (hiz), 16 DOUT (hiz), 17 ST (in), 18 NRZ (in), 19 EN (in), 20 VCC (power) hidden to VCC
2 alternate drawings of the same symbol

## WD1100-02
designator U?
footprint DIP-20
pins: 1 NRZ (in), 2 SKPEN (in), 3 WCLK (in), 4 WCLK (in), 5 RWC (in), 6 CS (in), 7 DRQCLK (in), 8 INTCLK (in), 10 GND (power) hidden to GND, 11 NOM (out), 12 LATE (out), 13 EARLY (out), 14 DRQ (out), 15 INTRQ (out), 16 MFM (out), 17 MR (in), 18 A1 (in), 19 A0 (in), 20 VCC (power) hidden to VCC
2 alternate drawings of the same symbol

## WD1100-03
designator U?
footprint DIP-20
pins: 1 RCLK (in), 2 DIN (in), 3 RCLK (in), 4 CLKIN (in), 5 DOUT (out), 8 TEST1 (out), 9 ENDET (in), 10 GND (power) hidden to GND, 11 TEST2 (out), 12 DCLK (out), 14 QOUT (out), 15 AMDET (out), 16 AMDET (out), 18 CP (in), 19 RST (in), 20 VCC (power) hidden to VCC
2 alternate drawings of the same symbol

## WD1100-04
designator U?
footprint DIP-20
pins: 1 DIN (in), 2 DOCK (in), 3 SHFCLK (in), 6 CWE (out), 7 DOCE (in), 8 CRCIZ (in), 10 GND (power) hidden to GND, 11 DOUT (out), 12 SKCLK (out), 13 CRCOK (out), 14 WCLK (in), 15 TIMCLK (out), 16 CRCOK (out), 20 VCC (power) hidden to VCC
2 alternate drawings of the same symbol

## WD1100-05
designator U?
footprint DIP-20
pins: 1 D0 (in), 2 D1 (in), 3 D2 (in), 4 D3 (in), 5 D4 (in), 6 D5 (in), 7 D6 (in), 8 D7 (in), 9 SHFCLK (hiz), 10 GND (power) hidden to GND, 11 DCLK (in), 12 WCLK (in), 13 LD (out), 14 SHFCLK (hiz), 15 DOUT (hiz), 16 BDONE (hiz), 17 TEST (out), 19 EN (in), 20 VCC (power) hidden to VCC
2 alternate drawings of the same symbol

## WD1100-06
designator U?
footprint DIP-20
pins: 1 R/~{W} (in), 2 RCP (in), 3 WCP (out), 4 RDAT (in), 5 WDAT (in), 6 SEL (in), 7 ECCIZ (in), 9 ECCEN (out), 10 GND (power) hidden to GND, 11 RWCP (out), 12 BS (io), 13 CSE (out), 14 FBD (out), 15 DOUT (out), 16 EDOUT (out), 17 DCSS (in), 18 RBS (in), 19 WBS (in), 20 VCC (power) hidden to VCC
2 alternate drawings of the same symbol

## WD1100-07
designator U?
footprint DIP-20
pins: 1 WCL1 (in), 2 WCL2 (in), 3 RESET (in), 4 SACEN (in), 5 AMDET (in), 6 TIMCLK (out), 7 RCLK (in), 8 INDEX (in), 9 LINR (in), 10 GND (power) hidden to GND, 11 LINDEX (out), 12 WAIT (out), 13 CSAC (out), 14 AMOUT (out), 15 RBS (out), 16 RCP (out), 17 WAEN (in), 18 CS (in), 19 WCLK (in), 20 VCC (power) hidden to VCC
2 alternate drawings of the same symbol

## WD1100-09
designator U?
footprint DIP-20
pins: 1 DATA (in), 2 REF (in), 3 DIN (in), 4 OSC (in), 5 DRS1 (in), 6 HIFRQ (out), 7 DRS2 (in), 8 DRUN (out), 9 DOUT (out), 10 GND (power) hidden to GND, 11 UP (out), 12 DOWN (out), 13 WDATA (in), 14 DS (out), 15 DRS3 (in), 16 WRITE (in), 17 DRS4 (in), 18 DMR (in), 19 RGATE (in), 20 VCC (power) hidden to VCC
2 alternate drawings of the same symbol

## WD1100-10
designator U?
footprint DIP-20
pins: 1 RD (in), 2 2*DR (in), 3 MR (in), 4 FDCLK2 (out), 5 EAREN (out), 6 NOMEN (out), 7 LATEN (out), 8 RG (in), 9 DOUT (out), 10 GND (power) hidden to GND, 13 EARLY (in), 14 LATE (in), 15 WC (out), 16 FDCLK1 (out), 17 WG (in), 18 WPEN (in), 19 WD (in), 20 VCC (power) hidden to VCC
2 alternate drawings of the same symbol

## WD1100-11
designator U?
footprint DIP-40
pins: 1 DRD1 (in), 2 DRD2 (in), 3 DRD3 (in), 4 DRD4 (in), 5 DRH (out), 6 DRL (out), 7 HD2 (out), 8 HD1 (out), 9 HD0 (out), 10 MR (in), 11 BCS (out), 12 BCR (out), 13 RD (out), 14 BRDY (out), 15 DRUN (out), 16 CS1 (in), 17 WE (in), 18 RE (in), 19 DRADJ (in), 20 GND (power) hidden to GND, 21 RDADJ (in), 22 A21 (in), 23 A11 (in), 24 A01 (in), 25 D0 (hiz), 26 D1 (hiz), 27 D2 (hiz), 28 D3 (hiz), 29 D4 (hiz), 30 D5 (hiz), 31 D6 (hiz), 32 BCLR (in), 33 RCE (out), 34 A5 (out), 35 A4 (out), 36 A3 (out), 37 A2 (out), 38 A1 (out), 39 A0 (out), 40 VCC (power) hidden to VCC
2 alternate drawings of the same symbol

## WD1100-12
designator U?
footprint DIP-20
pins: 1 NRZ (in), 2 SKPEN (in), 3 WCLK (in), 4 WCLK (in), 5 RWC (in), 6 CS (in), 7 DRQCLK (in), 8 INTCLK (in), 9 2*DR (in), 10 GND (power) hidden to GND, 11 NOM (out), 12 LATE (out), 13 EARLY (out), 14 DRQ (out), 15 INTRQ (out), 16 MFM (out), 17 MR (in), 18 A1 (in), 19 A0 (in), 20 VCC (power) hidden to VCC
2 alternate drawings of the same symbol

## WD1100-13
designator U?
footprint DIP-20
pins: 1 ERROR (out), 2 NC, 3 PRESET (in), 4 CS (in), 5 RE (in), 6 WE (in), 7 ECC/~{D} (in), 8 BUSY (out), 9 D6 (hiz), 10 GND (power) hidden to GND, 11 CLK (in), 12 D4 (hiz), 13 D2 (hiz), 14 D0 (hiz), 15 D1 (hiz), 16 D3 (hiz), 17 D5 (hiz), 18 D7 (hiz), 19 LONG (in), 20 VCC (power) hidden to VCC
2 alternate drawings of the same symbol

## WD1100-14
designator U?
footprint DIP-20
pins: 1 DB3 (hiz), 2 DB4 (hiz), 3 DB5 (hiz), 4 DB6 (hiz), 5 DB7 (hiz), 6 RE (in), 7 WE (in), 8 MR (in), 9 DIR (in), 10 GND (power) hidden to GND, 11 S/~{P} (in), 12 SD (hiz), 13 D/~{E} (in), 14 SO/DRQ (out), 15 LP/LD (io), 16 CLK (in), 17 DB0 (hiz), 18 DB1 (hiz), 19 DB2 (hiz), 20 VCC (power) hidden to VCC
2 alternate drawings of the same symbol

## WD1510
designator U?
footprint DIP-28
pins: 1 GND (power) hidden to GND, 2 EMPTY (out), 3 CSA (in), 4 ~{128}/32 (in), 5 MR (in), 6 PA0 (io), 7 PB0 (io), 8 PA1 (io), 9 PB1 (io), 10 PA2 (io), 11 PB2 (io), 12 PA3 (io), 13 PB3 (io), 14 PA4 (io), 15 PB4 (io), 16 VCC (power) hidden to VCC, 17 PA5 (io), 18 PB5 (io), 19 PA6 (io), 20 PB6 (io), 21 PA7 (io), 22 PB7 (io), 23 PA8 (io), 24 PB8 (io), 25 DIR (in), 27 CSB (in), 28 FULL (out)
2 alternate drawings of the same symbol

## WD1511
designator U?
footprint DIP-20
pins: 1 RESET (in), 2 CSA0 (out), 3 CSA1 (out), 4 CSA2 (out), 5 CSA3 (out), 6 CSB0 (out), 7 CSB1 (out), 8 CSB2 (out), 9 CSB3 (out), 10 GND (power) hidden to GND, 11 2/~{4}B (in), 12 2/~{4}A (in), 13 EXSTRO (in), 14 FI/~{O} (in), 15 DIR (in), 16 FULL (in), 17 EMPTY (in), 18 CLKB (in), 19 CLKA (in), 20 VCC (power) hidden to VCC
2 alternate drawings of the same symbol

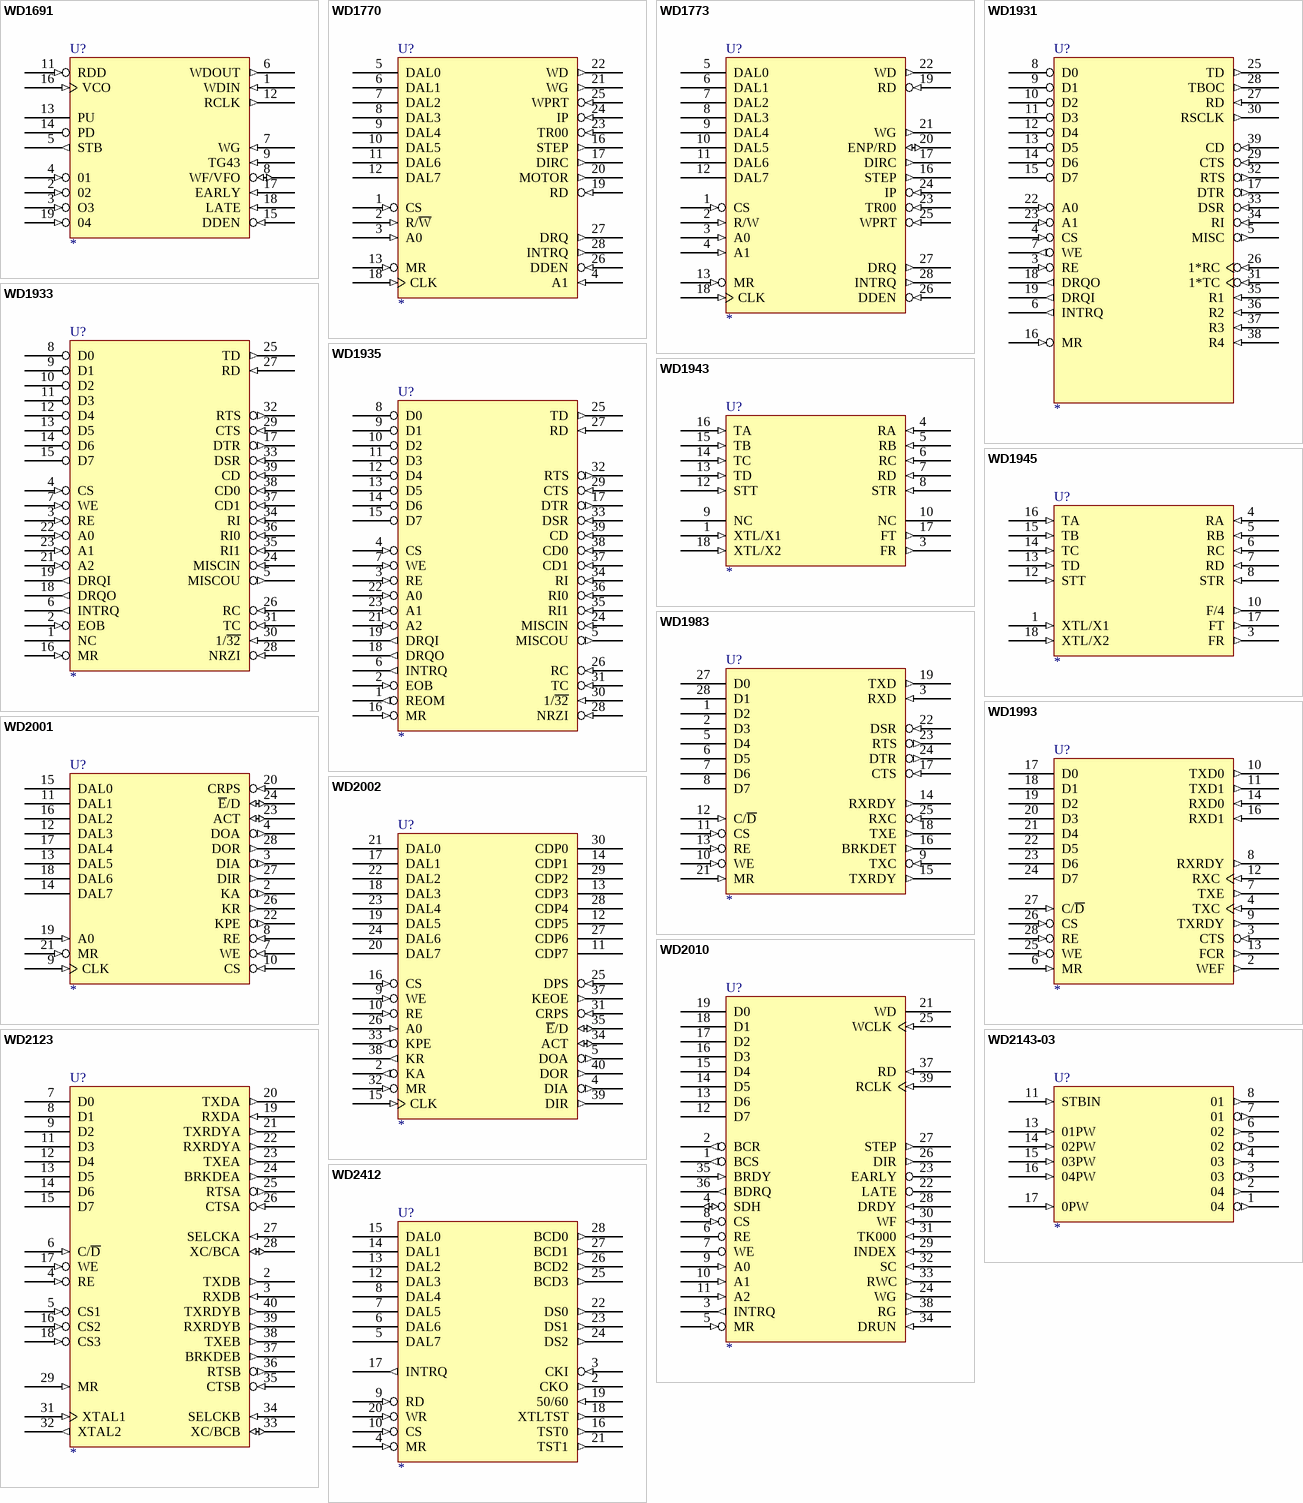
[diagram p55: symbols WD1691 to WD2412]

## WD1691
designator U?
footprint DIP-20
pins: 1 WDIN (in), 2 02 (in), 3 O3 (in), 4 01 (in), 5 STB (out), 6 WDOUT (out), 7 WG (in), 8 WF/VFO (io), 9 TG43 (in), 10 GND (power) hidden to GND, 11 RDD (in), 12 RCLK (out), 13 PU (hiz), 14 PD (hiz), 15 DDEN (in), 16 VCO (in), 17 EARLY (in), 18 LATE (in), 19 04 (in), 20 VCC (power) hidden to VCC
2 alternate drawings of the same symbol

## WD1770
designator U?
footprint DIP-28
pins: 1 CS (in), 2 R/~{W} (in), 3 A0 (in), 4 A1 (in), 5 DAL0 (hiz), 6 DAL1 (hiz), 7 DAL2 (hiz), 8 DAL3 (hiz), 9 DAL4 (hiz), 10 DAL5 (hiz), 11 DAL6 (hiz), 12 DAL7 (hiz), 13 MR (in), 14 GND (power) hidden to GND, 15 VCC (power) hidden to VCC, 16 STEP (out), 17 DIRC (out), 18 CLK (in), 19 RD (in), 20 MOTOR (out), 21 WG (out), 22 WD (out), 23 TR00 (in), 24 IP (in), 25 WPRT (in), 26 DDEN (in), 27 DRQ (out), 28 INTRQ (out)
2 alternate drawings of the same symbol

## WD1773
designator U?
footprint DIP-28
pins: 1 CS (in), 2 R/W (in), 3 A0 (in), 4 A1 (in), 5 DAL0 (hiz), 6 DAL1 (hiz), 7 DAL2 (hiz), 8 DAL3 (hiz), 9 DAL4 (hiz), 10 DAL5 (hiz), 11 DAL6 (hiz), 12 DAL7 (hiz), 13 MR (in), 14 GND (power) hidden to GND, 15 VCC (power) hidden to VCC, 16 STEP (out), 17 DIRC (out), 18 CLK (in), 19 RD (in), 20 ENP/RD (io), 21 WG (out), 22 WD (out), 23 TR00 (in), 24 IP (in), 25 WPRT (in), 26 DDEN (in), 27 DRQ (out), 28 INTRQ (out)
2 alternate drawings of the same symbol

## WD1931
designator U?
footprint DIP-40
pins: 3 RE (in), 4 CS (in), 5 MISC (out), 6 INTRQ (out), 7 WE (out), 8 D0 (hiz), 9 D1 (hiz), 10 D2 (hiz), 11 D3 (hiz), 12 D4 (hiz), 13 D5 (hiz), 14 D6 (hiz), 15 D7 (hiz), 16 MR (in), 17 DTR (out), 18 DRQO (out), 19 DRQI (out), 20 GND (power) hidden to GND, 22 A0 (in), 23 A1 (in), 24 +12 (power) hidden to +12, 25 TD (out), 26 1*RC (in), 27 RD (in), 28 TBOC (out), 29 CTS (in), 30 RSCLK (out), 31 1*TC (in), 32 RTS (out), 33 DSR (in), 34 RI (in), 35 R1 (in), 36 R2 (in), 37 R3 (in), 38 R4 (in), 39 CD (in), 40 VCC (power) hidden to VCC
2 alternate drawings of the same symbol

## WD1933
designator U?
footprint DIP-40
pins: 1 NC, 2 EOB (in), 3 RE (in), 4 CS (in), 5 MISCOU (out), 6 INTRQ (out), 7 WE (in), 8 D0 (hiz), 9 D1 (hiz), 10 D2 (hiz), 11 D3 (hiz), 12 D4 (hiz), 13 D5 (hiz), 14 D6 (hiz), 15 D7 (hiz), 16 MR (in), 17 DTR (out), 18 DRQO (out), 19 DRQI (out), 20 GND (power) hidden to GND, 21 A2 (in), 22 A0 (in), 23 A1 (in), 24 MISCIN (in), 25 TD (out), 26 RC (in), 27 RD (in), 28 NRZI (in), 29 CTS (in), 30 1/~{32} (in), 31 TC (in), 32 RTS (out), 33 DSR (in), 34 RI (in), 35 RI1 (in), 36 RI0 (in), 37 CD1 (in), 38 CD0 (in), 39 CD (in), 40 VCC (power) hidden to VCC
2 alternate drawings of the same symbol

## WD1935
designator U?
footprint DIP-40
pins: 1 REOM (out), 2 EOB (in), 3 RE (in), 4 CS (in), 5 MISCOU (out), 6 INTRQ (out), 7 WE (in), 8 D0 (hiz), 9 D1 (hiz), 10 D2 (hiz), 11 D3 (hiz), 12 D4 (hiz), 13 D5 (hiz), 14 D6 (hiz), 15 D7 (hiz), 16 MR (in), 17 DTR (out), 18 DRQO (out), 19 DRQI (out), 20 GND (power) hidden to GND, 21 A2 (in), 22 A0 (in), 23 A1 (in), 24 MISCIN (in), 25 TD (out), 26 RC (in), 27 RD (in), 28 NRZI (in), 29 CTS (in), 30 1/~{32} (in), 31 TC (in), 32 RTS (out), 33 DSR (in), 34 RI (in), 35 RI1 (in), 36 RI0 (in), 37 CD1 (in), 38 CD0 (in), 39 CD (in), 40 VCC (power) hidden to VCC
2 alternate drawings of the same symbol

## WD1943
designator U?
footprint DIP-18
pins: 1 XTL/X1 (in), 2 VCC (power) hidden to VCC, 3 FR (out), 4 RA (in), 5 RB (in), 6 RC (in), 7 RD (in), 8 STR (in), 9 NC, 10 NC, 11 GND (power) hidden to GND, 12 STT (in), 13 TD (in), 14 TC (in), 15 TB (in), 16 TA (in), 17 FT (out), 18 XTL/X2 (in)
2 alternate drawings of the same symbol

## WD1945
designator U?
footprint DIP-18
pins: 1 XTL/X1 (in), 2 VCC (power) hidden to VCC, 3 FR (out), 4 RA (in), 5 RB (in), 6 RC (in), 7 RD (in), 8 STR (in), 10 F/4 (out), 11 GND (power) hidden to GND, 12 STT (in), 13 TD (in), 14 TC (in), 15 TB (in), 16 TA (in), 17 FT (out), 18 XTL/X2 (in)
2 alternate drawings of the same symbol

## WD1983
designator U?
footprint DIP-28
pins: 1 D2 (hiz), 2 D3 (hiz), 3 RXD (in), 4 GND (power) hidden to GND, 5 D4 (hiz), 6 D5 (hiz), 7 D6 (hiz), 8 D7 (hiz), 9 TXC (in), 10 WE (in), 11 CS (in), 12 C/~{D} (in), 13 RE (in), 14 RXRDY (out), 15 TXRDY (out), 16 BRKDET (out), 17 CTS (in), 18 TXE (out), 19 TXD (out), 21 MR (in), 22 DSR (in), 23 RTS (out), 24 DTR (out), 25 RXC (in), 26 VCC (power) hidden to VCC, 27 D0 (hiz), 28 D1 (hiz)
2 alternate drawings of the same symbol

## WD1993
designator U?
footprint DIP-28
pins: 1 GND (power) hidden to GND, 2 WEF (out), 3 CTS (in), 4 TXC (in), 6 MR (in), 7 TXE (out), 8 RXRDY (out), 9 TXRDY (out), 10 TXD0 (out), 11 TXD1 (out), 12 RXC (in), 13 FCR (out), 14 RXD0 (in), 15 VCC (power) hidden to VCC, 16 RXD1 (in), 17 D0 (hiz), 18 D1 (hiz), 19 D2 (hiz), 20 D3 (hiz), 21 D4 (hiz), 22 D5 (hiz), 23 D6 (hiz), 24 D7 (hiz), 25 WE (in), 26 CS (in), 27 C/~{D} (in), 28 RE (in)
2 alternate drawings of the same symbol

## WD2001
designator U?
footprint DIP-40
pins: 2 KA (out), 3 DIA (out), 4 DOA (out), 5 VCC (power) hidden to VCC, 6 +12 (power) hidden to +12, 7 WE (in), 8 RE (in), 9 CLK (in), 10 CS (in), 11 DAL1 (hiz), 12 DAL3 (hiz), 13 DAL5 (hiz), 14 DAL7 (hiz), 15 DAL0 (hiz), 16 DAL2 (hiz), 17 DAL4 (hiz), 18 DAL6 (hiz), 19 A0 (in), 20 CRPS (in), 21 MR (in), 22 KPE (out), 23 ACT (io), 24 ~{E}/D (io), 25 GND (power) hidden to GND, 26 KR (out), 27 DIR (out), 28 DOR (out)
2 alternate drawings of the same symbol

## WD2002
designator U?
footprint DIP-40
pins: 2 KA (out), 4 DIA (out), 5 DOA (out), 7 VCC (power) hidden to VCC, 8 +12 (power) hidden to +12, 9 WE (in), 10 RE (in), 11 CDP7 (hiz), 12 CDP5 (hiz), 13 CDP3 (hiz), 14 CDP1 (hiz), 15 CLK (in), 16 CS (in), 17 DAL1 (hiz), 18 DAL3 (hiz), 19 DAL5 (hiz), 20 DAL7 (hiz), 21 DAL0 (hiz), 22 DAL2 (hiz), 23 DAL4 (hiz), 24 DAL6 (hiz), 25 DPS (in), 26 A0 (in), 27 CDP6 (hiz), 28 CDP4 (hiz), 29 CDP2 (hiz), 30 CDP0 (hiz), 31 CRPS (in), 32 MR (in), 33 KPE (out), 34 ACT (io), 35 ~{E}/D (io), 36 GND (power) hidden to GND, 37 KEOE (out), 38 KR (out), 39 DIR (out), 40 DOR (out)
2 alternate drawings of the same symbol

## WD2010
designator U?
footprint DIP-40
pins: 1 BCS (out), 2 BCR (out), 3 INTRQ (out), 4 SDH (io), 5 MR (in), 6 RE (hiz), 7 WE (hiz), 8 CS (in), 9 A0 (in), 10 A1 (in), 11 A2 (in), 12 D7 (hiz), 13 D6 (hiz), 14 D5 (hiz), 15 D4 (hiz), 16 D3 (hiz), 17 D2 (hiz), 18 D1 (hiz), 19 D0 (hiz), 20 GND (power) hidden to GND, 21 WD (oc), 22 LATE (oc), 23 EARLY (oc), 24 WG (out), 25 WCLK (in), 26 DIR (out), 27 STEP (out), 28 DRDY (in), 29 INDEX (in), 30 WF (in), 31 TK000 (in), 32 SC (in), 33 RWC (out), 34 DRUN (in), 35 BRDY (in), 36 BDRQ (out), 37 RD (in), 38 RG (out), 39 RCLK (in), 40 VCC (power) hidden to VCC
2 alternate drawings of the same symbol

## WD2123
designator U?
footprint DIP-40
pins: 2 TXDB (out), 3 RXDB (in), 4 RE (in), 5 CS1 (in), 6 C/~{D} (in), 7 D0 (hiz), 8 D1 (hiz), 9 D2 (hiz), 10 GND (power) hidden to GND, 11 D3 (hiz), 12 D4 (hiz), 13 D5 (hiz), 14 D6 (hiz), 15 D7 (hiz), 16 CS2 (in), 17 WE (in), 18 CS3 (in), 19 RXDA (in), 20 TXDA (out), 21 TXRDYA (out), 22 RXRDYA (out), 23 TXEA (out), 24 BRKDEA (out), 25 RTSA (out), 26 CTSA (in), 27 SELCKA (in), 28 XC/BCA (io), 29 MR (in), 30 VCC (power) hidden to VCC, 31 XTAL1 (in), 32 XTAL2 (out), 33 XC/BCB (io), 34 SELCKB (in), 35 CTSB (in), 36 RTSB (out), 37 BRKDEB (out), 38 TXEB (out), 39 RXRDYB (out), 40 TXRDYB (out)
2 alternate drawings of the same symbol

## WD2143-03
designator U?
footprint DIP-18
pins: 1 04 (out), 2 04 (out), 3 03 (out), 4 03 (out), 5 02 (out), 6 02 (out), 7 01 (out), 8 01 (out), 9 GND (power) hidden to GND, 11 STBIN (in), 13 01PW (in), 14 02PW (in), 15 03PW (in), 16 04PW (in), 17 0PW (in), 18 VCC (power) hidden to VCC
2 alternate drawings of the same symbol

## WD2412
designator U?
footprint DIP-28
pins: 1 GND (power) hidden to GND, 2 CKO (out), 3 CKI (in), 4 MR (in), 5 DAL7 (hiz), 6 DAL6 (hiz), 7 DAL5 (hiz), 8 DAL4 (hiz), 9 RD (in), 10 CS (in), 11 VCC (power) hidden to VCC, 12 DAL3 (hiz), 13 DAL2 (hiz), 14 DAL1 (hiz), 15 DAL0 (hiz), 16 TST0 (out), 17 INTRQ (out), 18 XTLTST (out), 19 50/60 (in), 20 WR (in), 21 TST1 (out), 22 DS0 (out), 23 DS1 (out), 24 DS2 (out), 25 BCD3 (out), 26 BCD2 (out), 27 BCD1 (out), 28 BCD0 (out)
2 alternate drawings of the same symbol

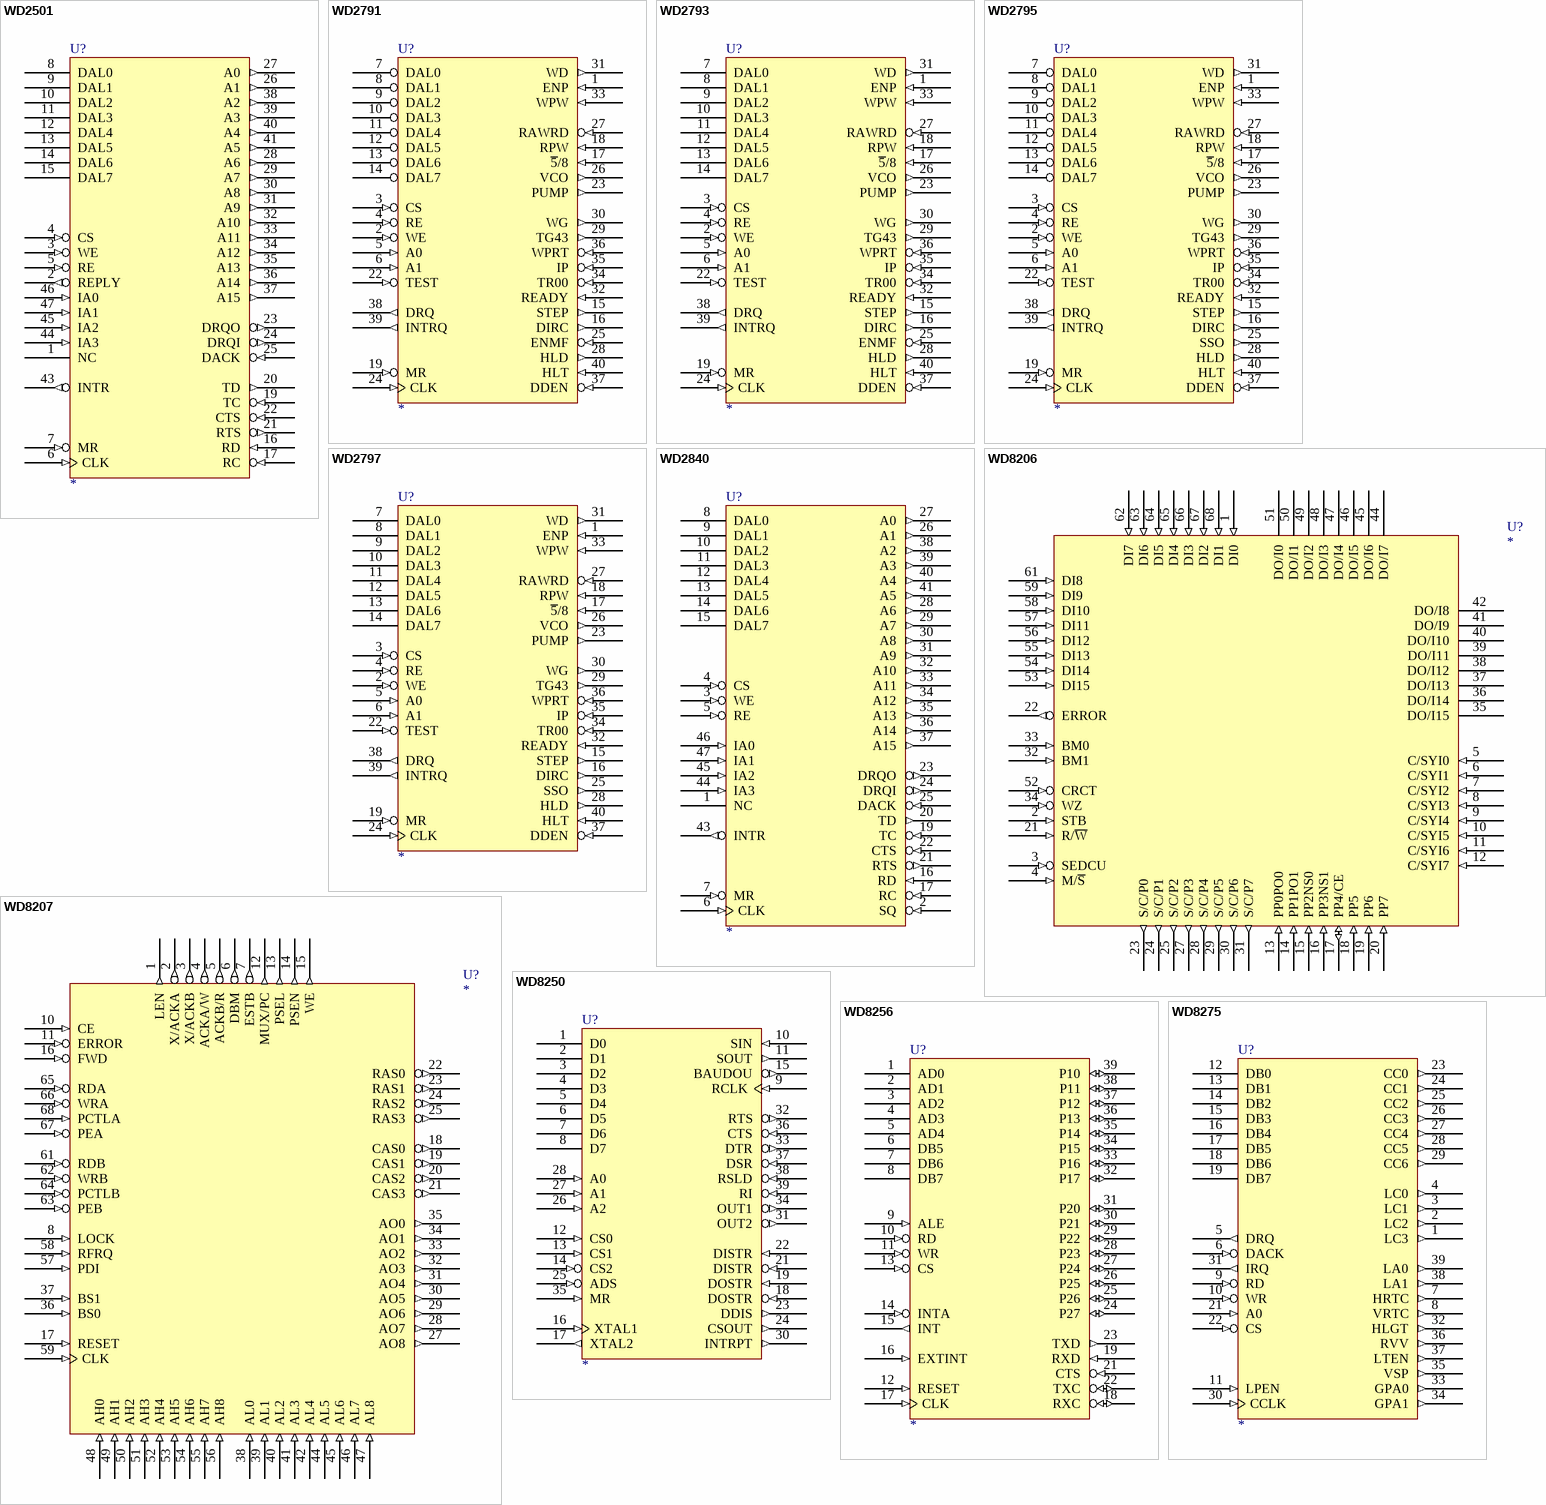
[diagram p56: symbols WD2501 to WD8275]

## WD2501
designator U?
footprint DIP-48
pins: 1 NC, 2 REPLY (out), 3 WE (in), 4 CS (in), 5 RE (in), 6 CLK (in), 7 MR (in), 8 DAL0 (hiz), 9 DAL1 (hiz), 10 DAL2 (hiz), 11 DAL3 (hiz), 12 DAL4 (hiz), 13 DAL5 (hiz), 14 DAL6 (hiz), 15 DAL7 (hiz), 16 RD (in), 17 RC (in), 18 GND (power) hidden to GND, 19 TC (in), 20 TD (out), 21 RTS (out), 22 CTS (in), 23 DRQO (out), 24 DRQI (out), 25 DACK (in), 26 A1 (out), 27 A0 (out), 28 A6 (out), 29 A7 (out), 30 A8 (out), 31 A9 (out), 32 A10 (out), 33 A11 (out), 34 A12 (out), 35 A13 (out), 36 A14 (out), 37 A15 (out), 38 A2 (out), 39 A3 (out), 40 A4 (out), 41 A5 (out), 42 +12 (power) hidden to +12, 43 INTR (out), 44 IA3 (in), 45 IA2 (in), 46 IA0 (in), 47 IA1 (in), 48 VCC (power) hidden to VCC
2 alternate drawings of the same symbol

## WD2791
designator U?
footprint DIP-40
pins: 1 ENP (in), 2 WE (in), 3 CS (in), 4 RE (in), 5 A0 (in), 6 A1 (in), 7 DAL0 (hiz), 8 DAL1 (hiz), 9 DAL2 (hiz), 10 DAL3 (hiz), 11 DAL4 (hiz), 12 DAL5 (hiz), 13 DAL6 (hiz), 14 DAL7 (hiz), 15 STEP (out), 16 DIRC (out), 17 ~{5}/8 (in), 18 RPW (in), 19 MR (in), 20 GND (power) hidden to GND, 21 VCC (power) hidden to VCC, 22 TEST (in), 23 PUMP (out), 24 CLK (in), 25 ENMF (in), 26 VCO (out), 27 RAWRD (in), 28 HLD (out), 29 TG43 (out), 30 WG (out), 31 WD (out), 32 READY (in), 33 WPW (in), 34 TR00 (in), 35 IP (in), 36 WPRT (in), 37 DDEN (in), 38 DRQ (out), 39 INTRQ (out), 40 HLT (in)
2 alternate drawings of the same symbol

## WD2793
designator U?
footprint DIP-40
pins: 1 ENP (in), 2 WE (in), 3 CS (in), 4 RE (in), 5 A0 (in), 6 A1 (in), 7 DAL0 (hiz), 8 DAL1 (hiz), 9 DAL2 (hiz), 10 DAL3 (hiz), 11 DAL4 (hiz), 12 DAL5 (hiz), 13 DAL6 (hiz), 14 DAL7 (hiz), 15 STEP (out), 16 DIRC (out), 17 ~{5}/8 (in), 18 RPW (in), 19 MR (in), 20 GND (power) hidden to GND, 21 VCC (power) hidden to VCC, 22 TEST (in), 23 PUMP (out), 24 CLK (in), 25 ENMF (in), 26 VCO (out), 27 RAWRD (in), 28 HLD (out), 29 TG43 (out), 30 WG (out), 31 WD (out), 32 READY (in), 33 WPW (in), 34 TR00 (in), 35 IP (in), 36 WPRT (in), 37 DDEN (in), 38 DRQ (out), 39 INTRQ (out), 40 HLT (in)
2 alternate drawings of the same symbol

## WD2795
designator U?
footprint DIP-40
pins: 1 ENP (in), 2 WE (in), 3 CS (in), 4 RE (in), 5 A0 (in), 6 A1 (in), 7 DAL0 (hiz), 8 DAL1 (hiz), 9 DAL2 (hiz), 10 DAL3 (hiz), 11 DAL4 (hiz), 12 DAL5 (hiz), 13 DAL6 (hiz), 14 DAL7 (hiz), 15 STEP (out), 16 DIRC (out), 17 ~{5}/8 (in), 18 RPW (in), 19 MR (in), 20 GND (power) hidden to GND, 21 VCC (power) hidden to VCC, 22 TEST (in), 23 PUMP (out), 24 CLK (in), 25 SSO (out), 26 VCO (out), 27 RAWRD (in), 28 HLD (out), 29 TG43 (out), 30 WG (out), 31 WD (out), 32 READY (in), 33 WPW (in), 34 TR00 (in), 35 IP (in), 36 WPRT (in), 37 DDEN (in), 38 DRQ (out), 39 INTRQ (out), 40 HLT (in)
2 alternate drawings of the same symbol

## WD2797
designator U?
footprint DIP-40
pins: 1 ENP (in), 2 WE (in), 3 CS (in), 4 RE (in), 5 A0 (in), 6 A1 (in), 7 DAL0 (hiz), 8 DAL1 (hiz), 9 DAL2 (hiz), 10 DAL3 (hiz), 11 DAL4 (hiz), 12 DAL5 (hiz), 13 DAL6 (hiz), 14 DAL7 (hiz), 15 STEP (out), 16 DIRC (out), 17 ~{5}/8 (in), 18 RPW (in), 19 MR (in), 20 GND (power) hidden to GND, 21 VCC (power) hidden to VCC, 22 TEST (in), 23 PUMP (out), 24 CLK (in), 25 SSO (out), 26 VCO (out), 27 RAWRD (in), 28 HLD (out), 29 TG43 (out), 30 WG (out), 31 WD (out), 32 READY (in), 33 WPW (in), 34 TR00 (in), 35 IP (in), 36 WPRT (in), 37 DDEN (in), 38 DRQ (out), 39 INTRQ (out), 40 HLT (in)
2 alternate drawings of the same symbol

## WD2840
designator U?
footprint DIP-48
pins: 1 NC, 2 SQ (in), 3 WE (in), 4 CS (in), 5 RE (in), 6 CLK (in), 7 MR (in), 8 DAL0 (hiz), 9 DAL1 (hiz), 10 DAL2 (hiz), 11 DAL3 (hiz), 12 DAL4 (hiz), 13 DAL5 (hiz), 14 DAL6 (hiz), 15 DAL7 (hiz), 16 RD (in), 17 RC (in), 18 GND (power) hidden to GND, 19 TC (in), 20 TD (out), 21 RTS (out), 22 CTS (in), 23 DRQO (out), 24 DRQI (out), 25 DACK (in), 26 A1 (out), 27 A0 (out), 28 A6 (out), 29 A7 (out), 30 A8 (out), 31 A9 (out), 32 A10 (out), 33 A11 (out), 34 A12 (out), 35 A13 (out), 36 A14 (out), 37 A15 (out), 38 A2 (out), 39 A3 (out), 40 A4 (out), 41 A5 (out), 42 +12 (power) hidden to +12, 43 INTR (out), 44 IA3 (in), 45 IA2 (in), 46 IA0 (in), 47 IA1 (in), 48 VCC (power) hidden to VCC
2 alternate drawings of the same symbol

## WD8206
designator U?
footprint JEDECA-68
pins: 1 DI0 (in), 2 STB (in), 3 SEDCU (in), 4 M/~{S} (in), 5 C/SYI0 (in), 6 C/SYI1 (in), 7 C/SYI2 (in), 8 C/SYI3 (in), 9 C/SYI4 (in), 10 C/SYI5 (in), 11 C/SYI6 (in), 12 C/SYI7 (in), 13 PP0PO0 (in), 14 PP1PO1 (in), 15 PP2NS0 (in), 16 PP3NS1 (in), 17 PP4/CE (io), 18 PP5 (in), 19 PP6 (in), 20 PP7 (in), 21 R/~{W} (in), 22 ERROR (out), 23 S/C/P0 (out), 24 S/C/P1 (out), 25 S/C/P2 (out), 26 GND (power) hidden to GND, 27 S/C/P3 (out), 28 S/C/P4 (out), 29 S/C/P5 (out), 30 S/C/P6 (out), 31 S/C/P7 (out), 32 BM1 (in), 33 BM0 (in), 34 WZ (in), 35 DO/I15 (hiz), 36 DO/I14 (hiz), 37 DO/I13 (hiz), 38 DO/I12 (hiz), 39 DO/I11 (hiz), 40 DO/I10 (hiz), 41 DO/I9 (hiz), 42 DO/I8 (hiz), 43 GND (power) hidden to GND, 44 DO/I7 (hiz), 45 DO/I6 (hiz), 46 DO/I5 (hiz), 47 DO/I4 (hiz), 48 DO/I3 (hiz), 49 DO/I2 (hiz), 50 DO/I1 (hiz), 51 DO/I0 (hiz), 52 CRCT (in), 53 DI15 (in), 54 DI14 (in), 55 DI13 (in), 56 DI12 (in), 57 DI11 (in), 58 DI10 (in), 59 DI9 (in), 60 VCC (power) hidden to VCC, 61 DI8 (in), 62 DI7 (in), 63 DI6 (in), 64 DI5 (in), 65 DI4 (in), 66 DI3 (in), 67 DI2 (in), 68 DI1 (in)
2 alternate drawings of the same symbol

## WD8207
designator U?
footprint JEDECA-68
pins: 1 LEN (out), 2 X/ACKA (out), 3 X/ACKB (out), 4 ACKA/W (out), 5 ACKB/R (out), 6 DBM (out), 7 ESTB (out), 8 LOCK (in), 9 VCC (power) hidden to VCC, 10 CE (in), 11 ERROR (in), 12 MUX/PC (out), 13 PSEL (out), 14 PSEN (out), 15 WE (out), 16 FWD (in), 17 RESET (in), 18 CAS0 (out), 19 CAS1 (out), 20 CAS2 (out), 21 CAS3 (out), 22 RAS0 (out), 23 RAS1 (out), 24 RAS2 (out), 25 RAS3 (out), 26 GND (power) hidden to GND, 27 AO8 (out), 28 AO7 (out), 29 AO6 (out), 30 AO5 (out), 31 AO4 (out), 32 AO3 (out), 33 AO2 (out), 34 AO1 (out), 35 AO0 (out), 36 BS0 (in), 37 BS1 (in), 38 AL0 (in), 39 AL1 (in), 40 AL2 (in), 41 AL3 (in), 42 AL4 (in), 43 VCC (power) hidden to VCC, 44 AL5 (in), 45 AL6 (in), 46 AL7 (in), 47 AL8 (in), 48 AH0 (in), 49 AH1 (in), 50 AH2 (in), 51 AH3 (in), 52 AH4 (in), 53 AH5 (in), 54 AH6 (in), 55 AH7 (in), 56 AH8 (in), 57 PDI (in), 58 RFRQ (in), 59 CLK (in), 60 GND (power) hidden to GND, 61 RDB (in), 62 WRB (in), 63 PEB (in), 64 PCTLB (in), 65 RDA (in), 66 WRA (in), 67 PEA (in), 68 PCTLA (in)
2 alternate drawings of the same symbol

## WD8250
designator U?
footprint DIP-40
pins: 1 D0 (hiz), 2 D1 (hiz), 3 D2 (hiz), 4 D3 (hiz), 5 D4 (hiz), 6 D5 (hiz), 7 D6 (hiz), 8 D7 (hiz), 9 RCLK (in), 10 SIN (in), 11 SOUT (out), 12 CS0 (in), 13 CS1 (in), 14 CS2 (in), 15 BAUDOU (out), 16 XTAL1 (in), 17 XTAL2 (out), 18 DOSTR (in), 19 DOSTR (in), 20 GND (power) hidden to GND, 21 DISTR (in), 22 DISTR (in), 23 DDIS (out), 24 CSOUT (out), 25 ADS (in), 26 A2 (in), 27 A1 (in), 28 A0 (in), 30 INTRPT (out), 31 OUT2 (out), 32 RTS (out), 33 DTR (out), 34 OUT1 (out), 35 MR (in), 36 CTS (in), 37 DSR (in), 38 RSLD (in), 39 RI (in), 40 VCC (power) hidden to VCC
2 alternate drawings of the same symbol

## WD8256
designator U?
footprint DIP-40
pins: 1 AD0 (hiz), 2 AD1 (hiz), 3 AD2 (hiz), 4 AD3 (hiz), 5 AD4 (hiz), 6 DB5 (hiz), 7 DB6 (hiz), 8 DB7 (hiz), 9 ALE (in), 10 RD (in), 11 WR (in), 12 RESET (in), 13 CS (in), 14 INTA (in), 15 INT (out), 16 EXTINT (in), 17 CLK (in), 18 RXC (io), 19 RXD (in), 20 GND (power) hidden to GND, 21 CTS (in), 22 TXC (io), 23 TXD (out), 24 P27 (io), 25 P26 (io), 26 P25 (io), 27 P24 (io), 28 P23 (io), 29 P22 (io), 30 P21 (io), 31 P20 (io), 32 P17 (io), 33 P16 (io), 34 P15 (io), 35 P14 (io), 36 P13 (io), 37 P12 (io), 38 P11 (io), 39 P10 (io), 40 VCC (power) hidden to VCC
2 alternate drawings of the same symbol

## WD8275
designator U?
footprint DIP-40
pins: 1 LC3 (out), 2 LC2 (out), 3 LC1 (out), 4 LC0 (out), 5 DRQ (out), 6 DACK (in), 7 HRTC (out), 8 VRTC (out), 9 RD (in), 10 WR (in), 11 LPEN (in), 12 DB0 (hiz), 13 DB1 (hiz), 14 DB2 (hiz), 15 DB3 (hiz), 16 DB4 (hiz), 17 DB5 (hiz), 18 DB6 (hiz), 19 DB7 (hiz), 20 GND (power) hidden to GND, 21 A0 (in), 22 CS (in), 23 CC0 (out), 24 CC1 (out), 25 CC2 (out), 26 CC3 (out), 27 CC4 (out), 28 CC5 (out), 29 CC6 (out), 30 CCLK (in), 31 IRQ (out), 32 HLGT (out), 33 GPA0 (out), 34 GPA1 (out), 35 VSP (out), 36 RVV (out), 37 LTEN (out), 38 LA1 (out), 39 LA0 (out), 40 VCC (power) hidden to VCC
2 alternate drawings of the same symbol

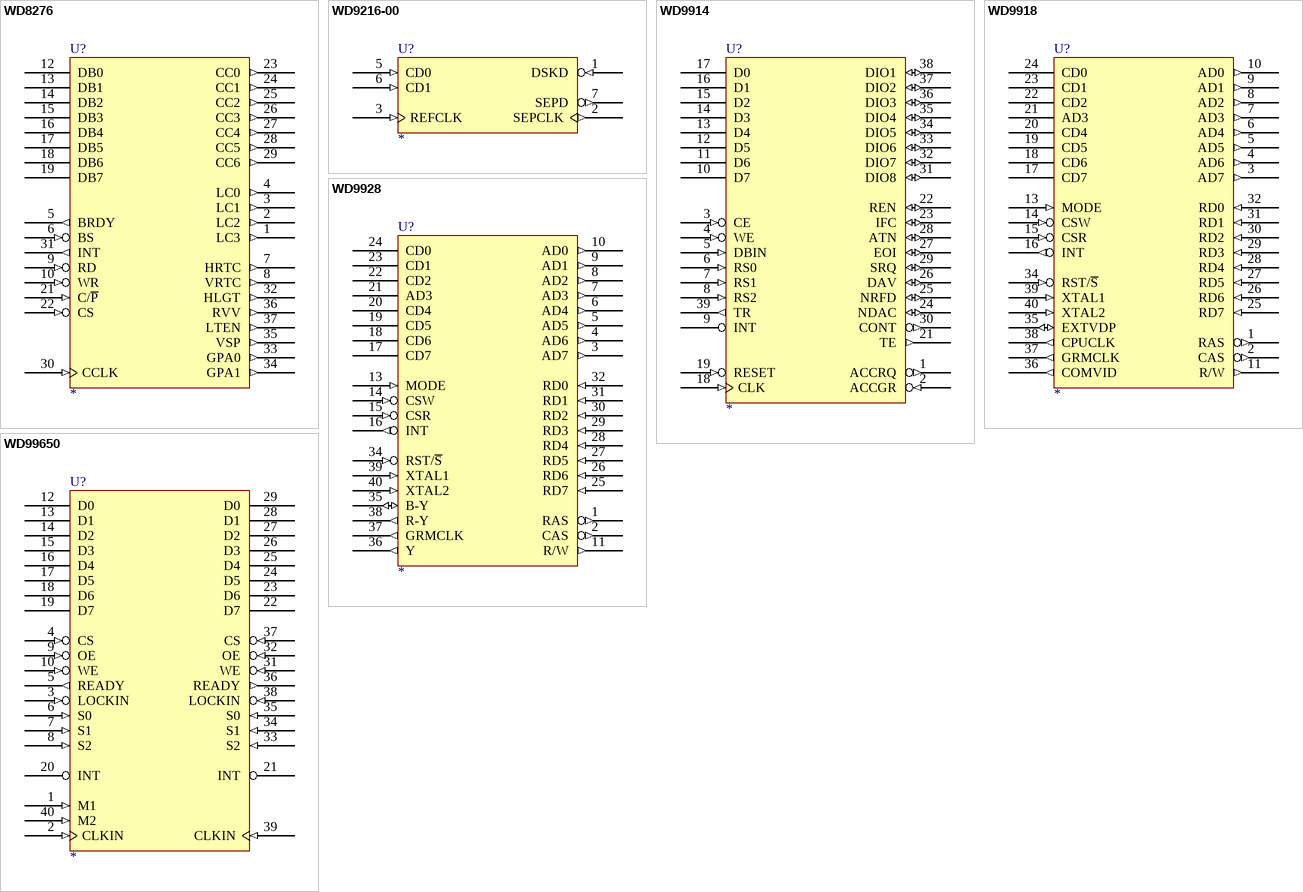
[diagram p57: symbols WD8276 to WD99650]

## WD8276
designator U?
footprint DIP-40
pins: 1 LC3 (out), 2 LC2 (out), 3 LC1 (out), 4 LC0 (out), 5 BRDY (out), 6 BS (in), 7 HRTC (out), 8 VRTC (out), 9 RD (in), 10 WR (in), 12 DB0 (hiz), 13 DB1 (hiz), 14 DB2 (hiz), 15 DB3 (hiz), 16 DB4 (hiz), 17 DB5 (hiz), 18 DB6 (hiz), 19 DB7 (hiz), 20 GND (power) hidden to GND, 21 C/~{P} (in), 22 CS (in), 23 CC0 (out), 24 CC1 (out), 25 CC2 (out), 26 CC3 (out), 27 CC4 (out), 28 CC5 (out), 29 CC6 (out), 30 CCLK (in), 31 INT (out), 32 HLGT (out), 33 GPA0 (out), 34 GPA1 (out), 35 VSP (out), 36 RVV (out), 37 LTEN (out), 40 VCC (power) hidden to VCC
2 alternate drawings of the same symbol

## WD9216-00
designator U?
footprint DIP-8
pins: 1 DSKD (in), 2 SEPCLK (out), 3 REFCLK (in), 4 GND (power) hidden to GND, 5 CD0 (in), 6 CD1 (in), 7 SEPD (out), 8 VCC (power) hidden to VCC
2 alternate drawings of the same symbol

## WD9914
designator U?
footprint DIP-40
pins: 1 ACCRQ (out), 2 ACCGR (in), 3 CE (in), 4 WE (in), 5 DBIN (in), 6 RS0 (in), 7 RS1 (in), 8 RS2 (in), 9 INT (oc), 10 D7 (hiz), 11 D6 (hiz), 12 D5 (hiz), 13 D4 (hiz), 14 D3 (hiz), 15 D2 (hiz), 16 D1 (hiz), 17 D0 (hiz), 18 CLK (in), 19 RESET (in), 20 GND (power) hidden to GND, 21 TE (out), 22 REN (io), 23 IFC (io), 24 NDAC (io), 25 NRFD (io), 26 DAV (io), 27 EOI (io), 28 ATN (io), 29 SRQ (io), 30 CONT (out), 31 DIO8 (io), 32 DIO7 (io), 33 DIO6 (io), 34 DIO5 (io), 35 DIO4 (io), 36 DIO3 (io), 37 DIO2 (io), 38 DIO1 (io), 39 TR (out), 40 VCC (power) hidden to VCC
2 alternate drawings of the same symbol

## WD9918
designator U?
footprint DIP-40
pins: 1 RAS (out), 2 CAS (out), 3 AD7 (out), 4 AD6 (out), 5 AD5 (out), 6 AD4 (out), 7 AD3 (out), 8 AD2 (out), 9 AD1 (out), 10 AD0 (out), 11 R/W (out), 12 GND (power) hidden to GND, 13 MODE (in), 14 CSW (in), 15 CSR (in), 16 INT (out), 17 CD7 (hiz), 18 CD6 (hiz), 19 CD5 (hiz), 20 CD4 (hiz), 21 AD3 (hiz), 22 CD2 (hiz), 23 CD1 (hiz), 24 CD0 (hiz), 25 RD7 (in), 26 RD6 (in), 27 RD5 (in), 28 RD4 (in), 29 RD3 (in), 30 RD2 (in), 31 RD1 (in), 32 RD0 (in), 33 VCC (power) hidden to VCC, 34 RST/~{S} (in), 35 EXTVDP (io), 36 COMVID (out), 37 GRMCLK (out), 38 CPUCLK (out), 39 XTAL1 (in), 40 XTAL2 (in)
2 alternate drawings of the same symbol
